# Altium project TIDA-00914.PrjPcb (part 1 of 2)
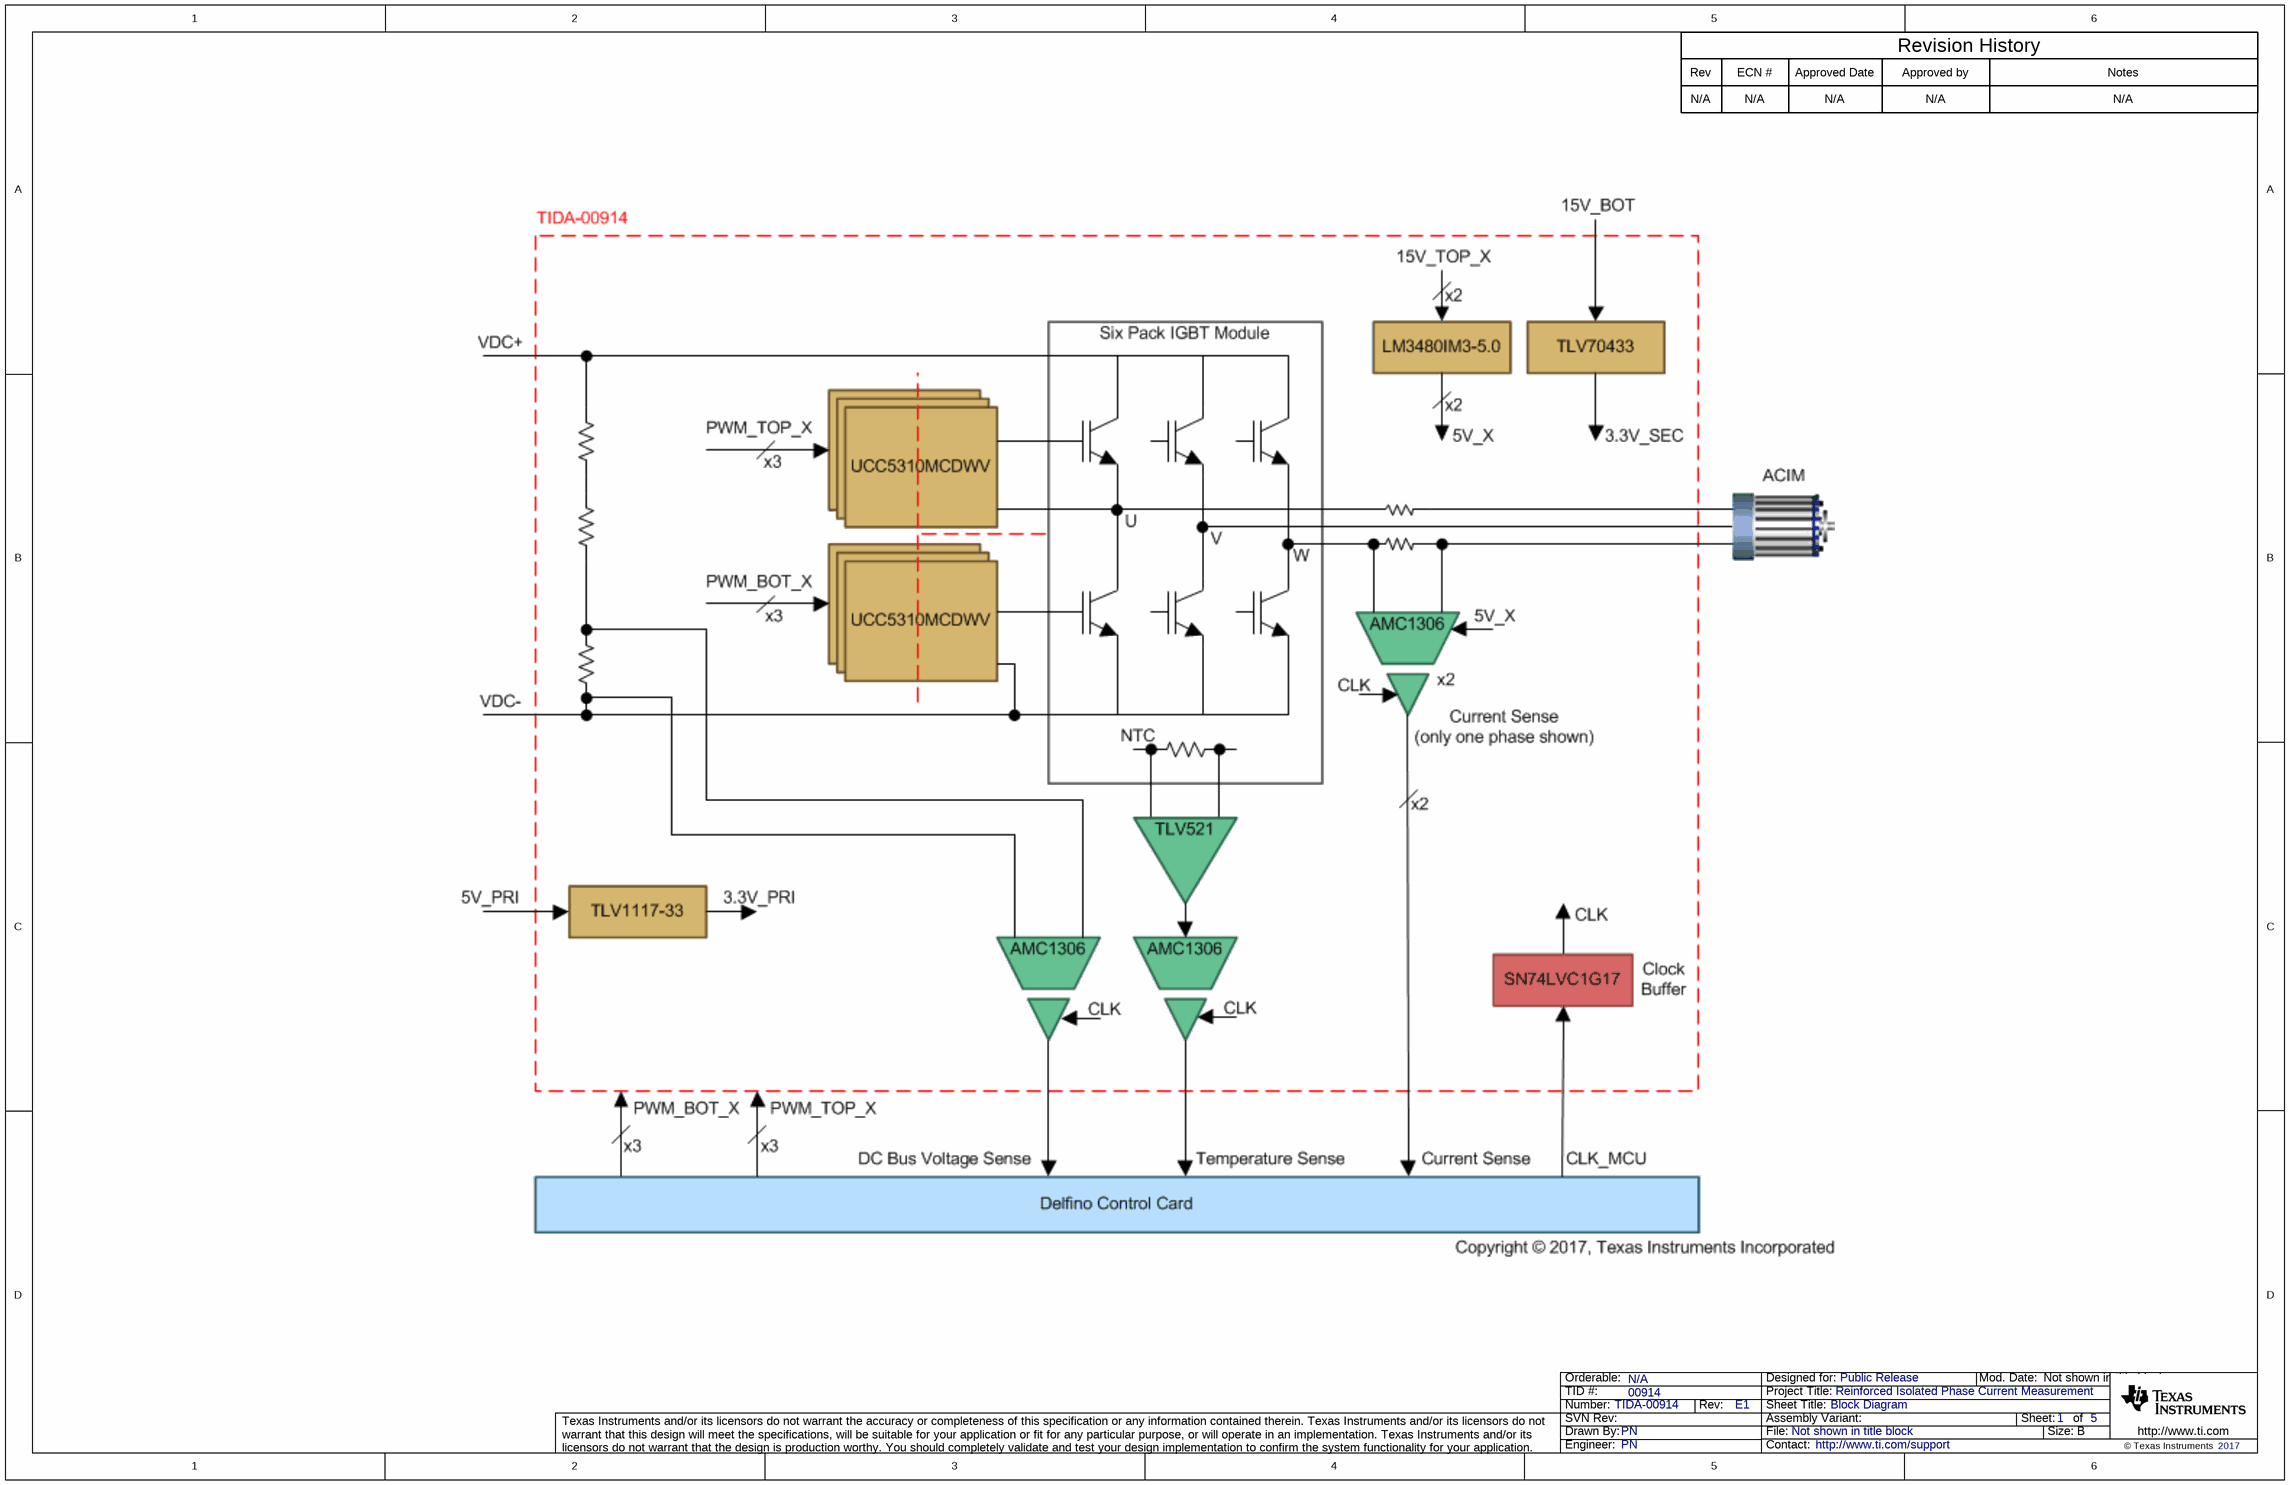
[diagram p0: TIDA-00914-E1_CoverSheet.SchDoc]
CopyrightYear: 2017; EVM_orderable: N/A; PCB_Rev: E1; PRJ_Customer: Public Release; PRJ_Engineer: PN; PRJ_Number: TIDA-00914; PRJ_Title: Reinforced Isolated Phase Current Measurement; SCH_Rev: E1; TechSupport: http://www.ti.com/support; TID: 00914
5 sheets, 303 parts. Net scope: flat (ports and power ports of the same name join across sheets).
Board file: TIDA-00914-E1.PcbDoc
Sheets:
  TIDA-00914-E1_CoverSheet.SchDoc
  TIDA-00914-E1_Gate drivers.SchDoc
  TIDA-00914-E1_IGBT Module, Temp and DC link sense.SchDoc
  TIDA-00914-E1_Current sense, MCU Interface.SchDoc
  TIDA-00914-E1_EVM_Hardware.SchDoc

## Sheet TIDA-00914-E1_CoverSheet.SchDoc: Block Diagram
size 431 x 279 mm; Date: Not shown in title block; ApprovedBy: Not shown in title block; CheckedBy: Not shown in title block; Author: Not shown in title block; CompanyName: Not shown in title block; DrawnBy: PN; Engineer: PN; Organization: Not shown in title block; Address1: Not shown in title block; Address2: Not shown in title block; Address3: Not shown in title block; Address4: Not shown in title block; DocumentNumber: 1; Revision: Use project parameter SCH_Rev; SheetNumber: 1; SheetTotal: 5; PageSetup: Record=PageOptions¦CenterHorizontal=True¦CenterVertical=True¦PrintScale=1.00¦XCorrection=1.00¦YCorrection=1.00¦PrintKind=0¦BorderSize=5000000¦LeftOffset=0¦BottomOffset=0¦Orientation=2¦PaperLength=1000¦PaperWidth=1000¦Scale=100¦PaperSource=15¦PrintQuality=600¦MediaType=1¦DitherType=10¦PaperKind=Letter¦PrintScaleMode=1

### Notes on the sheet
- Rev
- N/A
- ECN #
- Approved Date
- Approved by
- Revision History
- Notes

## Sheet TIDA-00914-E1_Gate drivers.SchDoc: Gate Drivers
size 431 x 279 mm; Date: Not shown in title block; ApprovedBy: Not shown in title block; CheckedBy: Not shown in title block; Author: Not shown in title block; CompanyName: Not shown in title block; DrawnBy: PN; Engineer: PN; Organization: Not shown in title block; Address1: Not shown in title block; Address2: Not shown in title block; Address3: Not shown in title block; Address4: Not shown in title block; DocumentNumber: 1; Revision: Use project parameter SCH_Rev; SheetNumber: 2; SheetTotal: 5; PageSetup: Record=PageOptions¦CenterHorizontal=True¦CenterVertical=True¦PrintScale=1.00¦XCorrection=1.00¦YCorrection=1.00¦PrintKind=0¦BorderSize=5000000¦LeftOffset=0¦BottomOffset=0¦Orientation=2¦PaperLength=1000¦PaperWidth=1000¦Scale=100¦PaperSource=15¦PrintQuality=600¦MediaType=1¦DitherType=10¦PaperKind=Letter¦PrintScaleMode=1
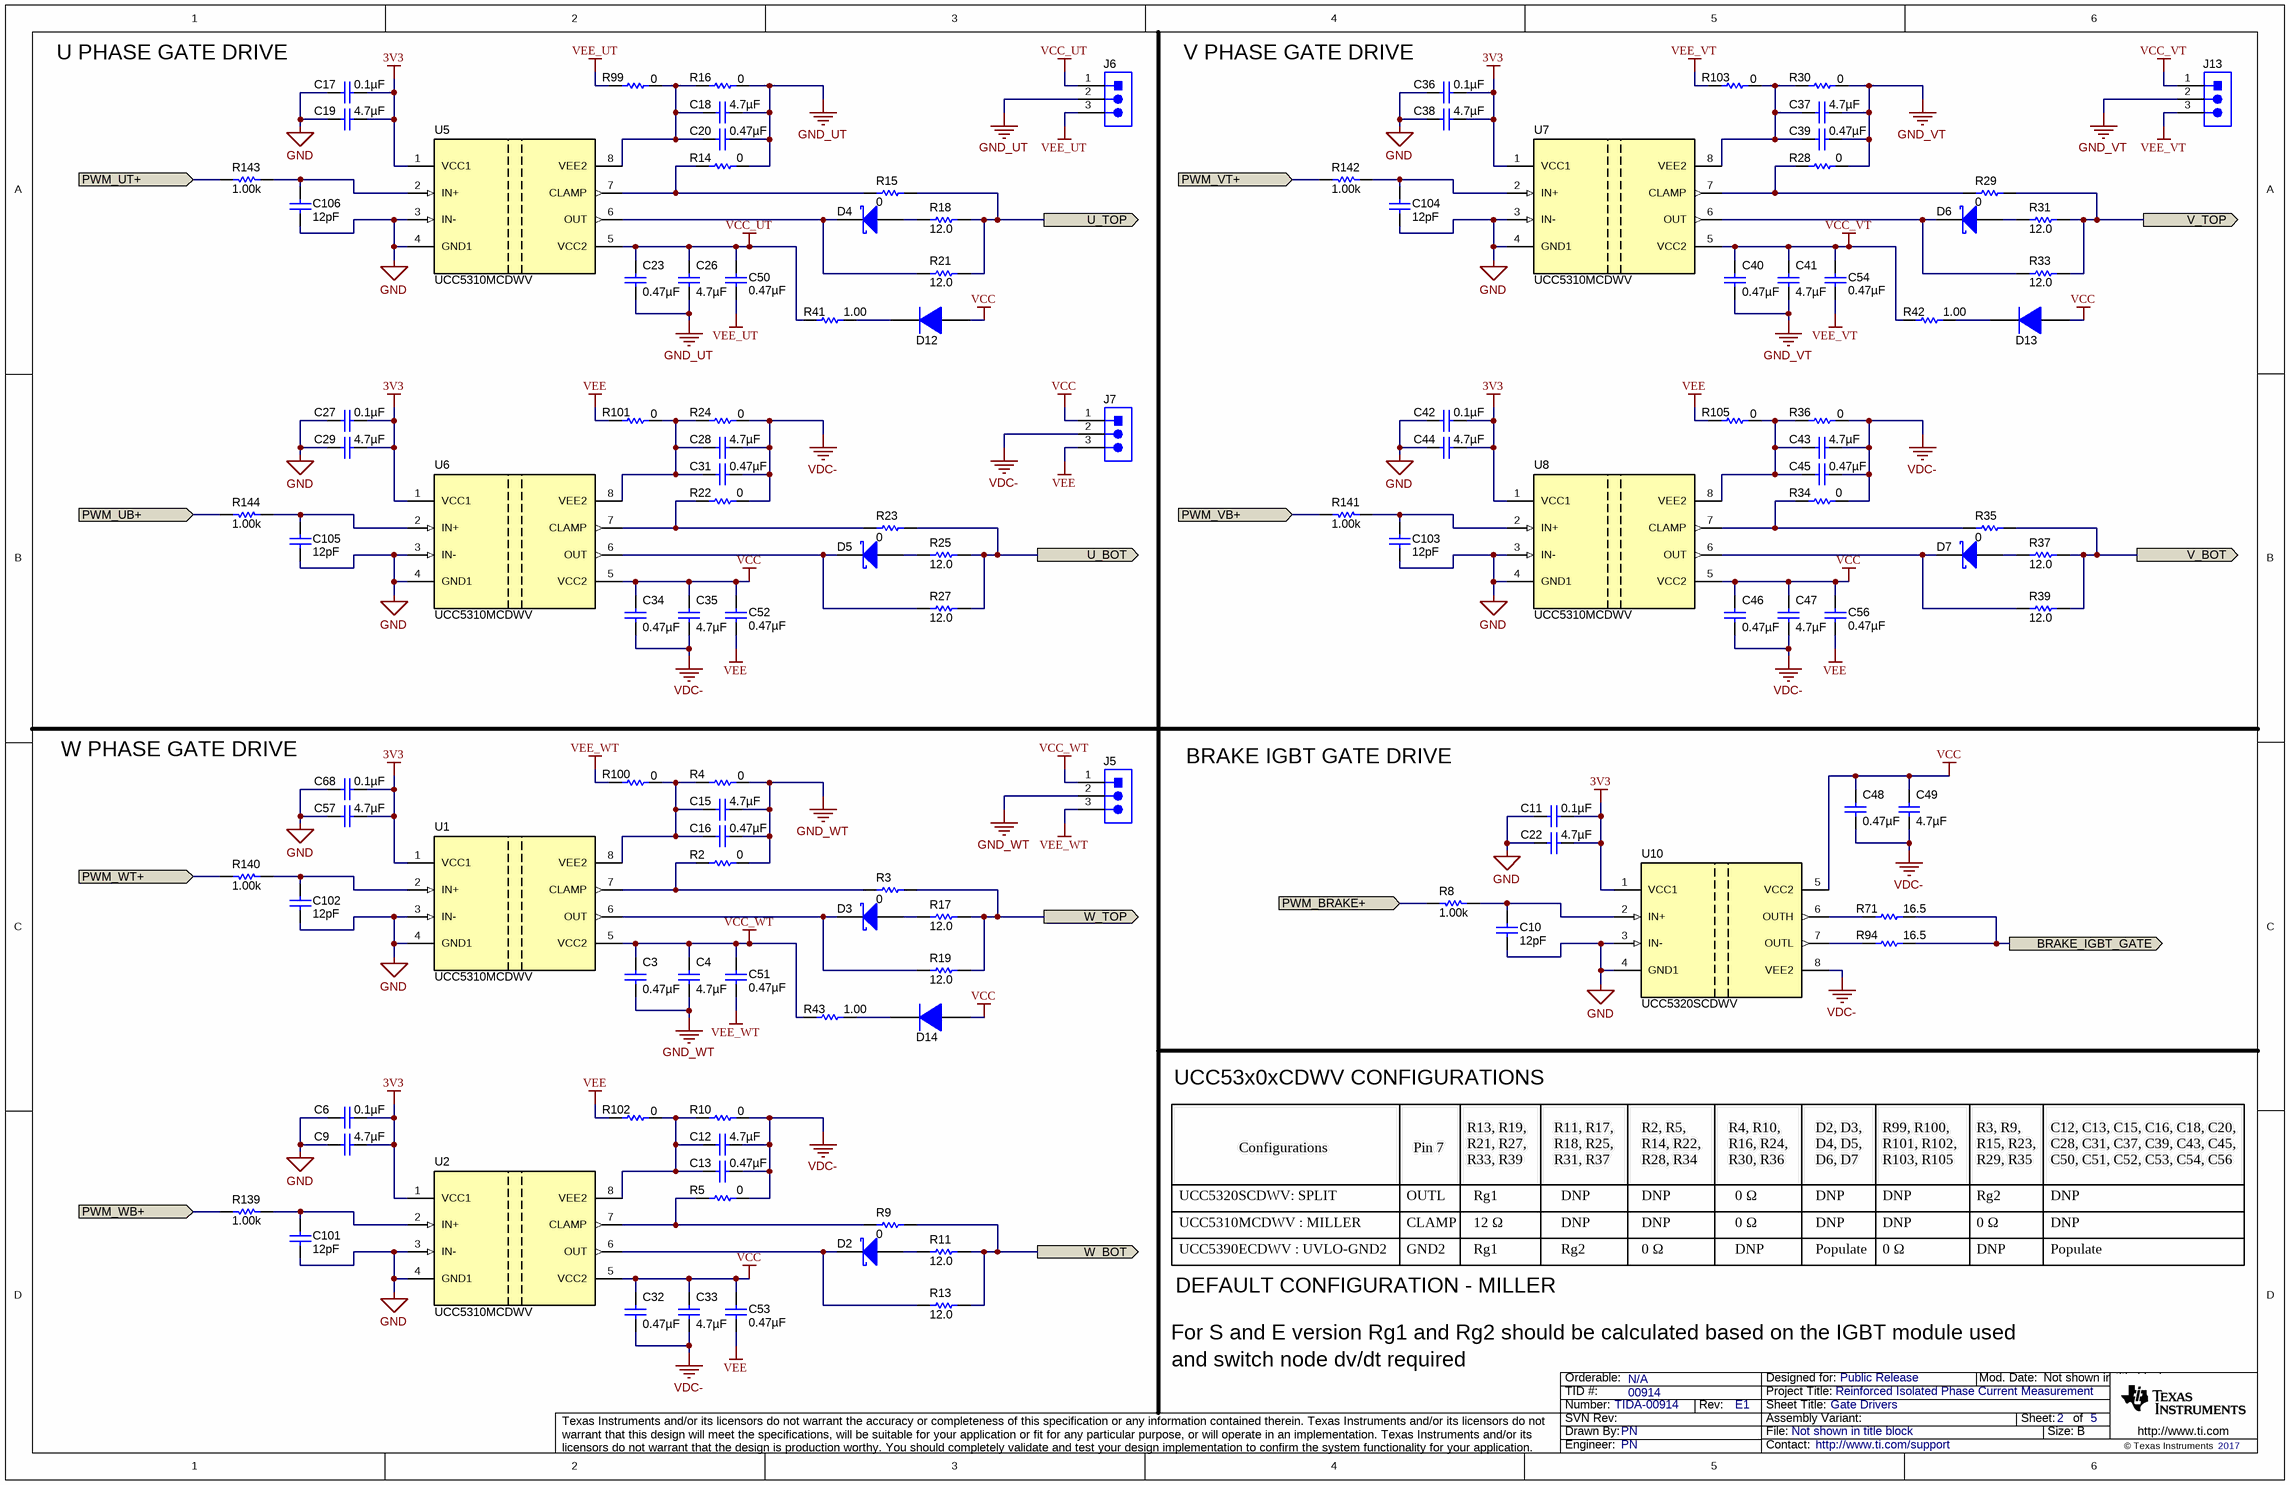
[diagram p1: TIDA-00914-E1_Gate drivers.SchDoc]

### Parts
C3  ValueDisplayed: 0.47µF  [0603]  (hidden comment: C1608X7R1H474K080AC)
C4  ValueDisplayed: 4.7µF  [0805_HV]  (hidden comment: C2012X7R1V475K125AC)
C6  ValueDisplayed: 0.1µF  [0603]  (hidden comment: C1608X7R1H104K)
C9  ValueDisplayed: 4.7µF  [0805_HV]  (hidden comment: C2012X7R1V475K125AC)
C10  ValueDisplayed: 12pF  [0603]  (hidden comment: GRM1885C1H120JA01D)
C11  ValueDisplayed: 0.1µF  [0603]  (hidden comment: C1608X7R1H104K)
C12  ValueDisplayed: 4.7µF  [0805_HV]  (hidden comment: C2012X7R1V475K125AC)
C13  ValueDisplayed: 0.47µF  [0603]  (hidden comment: C1608X7R1H474K080AC)
C15  ValueDisplayed: 4.7µF  [0805_HV]  (hidden comment: C2012X7R1V475K125AC)
C16  ValueDisplayed: 0.47µF  [0603]  (hidden comment: C1608X7R1H474K080AC)
C17  ValueDisplayed: 0.1µF  [0603]  (hidden comment: C1608X7R1H104K)
C18  ValueDisplayed: 4.7µF  [0805_HV]  (hidden comment: C2012X7R1V475K125AC)
C19  ValueDisplayed: 4.7µF  [0805_HV]  (hidden comment: C2012X7R1V475K125AC)
C20  ValueDisplayed: 0.47µF  [0603]  (hidden comment: C1608X7R1H474K080AC)
C22  ValueDisplayed: 4.7µF  [0805_HV]  (hidden comment: C2012X7R1V475K125AC)
C23  ValueDisplayed: 0.47µF  [0603]  (hidden comment: C1608X7R1H474K080AC)
C26  ValueDisplayed: 4.7µF  [0805_HV]  (hidden comment: C2012X7R1V475K125AC)
C27  ValueDisplayed: 0.1µF  [0603]  (hidden comment: C1608X7R1H104K)
C28  ValueDisplayed: 4.7µF  [0805_HV]  (hidden comment: C2012X7R1V475K125AC)
C29  ValueDisplayed: 4.7µF  [0805_HV]  (hidden comment: C2012X7R1V475K125AC)
C31  ValueDisplayed: 0.47µF  [0603]  (hidden comment: C1608X7R1H474K080AC)
C32  ValueDisplayed: 0.47µF  [0603]  (hidden comment: C1608X7R1H474K080AC)
C33  ValueDisplayed: 4.7µF  [0805_HV]  (hidden comment: C2012X7R1V475K125AC)
C34  ValueDisplayed: 0.47µF  [0603]  (hidden comment: C1608X7R1H474K080AC)
C35  ValueDisplayed: 4.7µF  [0805_HV]  (hidden comment: C2012X7R1V475K125AC)
C36  ValueDisplayed: 0.1µF  [0603]  (hidden comment: C1608X7R1H104K)
C37  ValueDisplayed: 4.7µF  [0805_HV]  (hidden comment: C2012X7R1V475K125AC)
C38  ValueDisplayed: 4.7µF  [0805_HV]  (hidden comment: C2012X7R1V475K125AC)
C39  ValueDisplayed: 0.47µF  [0603]  (hidden comment: C1608X7R1H474K080AC)
C40  ValueDisplayed: 0.47µF  [0603]  (hidden comment: C1608X7R1H474K080AC)
C41  ValueDisplayed: 4.7µF  [0805_HV]  (hidden comment: C2012X7R1V475K125AC)
C42  ValueDisplayed: 0.1µF  [0603]  (hidden comment: C1608X7R1H104K)
C43  ValueDisplayed: 4.7µF  [0805_HV]  (hidden comment: C2012X7R1V475K125AC)
C44  ValueDisplayed: 4.7µF  [0805_HV]  (hidden comment: C2012X7R1V475K125AC)
C45  ValueDisplayed: 0.47µF  [0603]  (hidden comment: C1608X7R1H474K080AC)
C46  ValueDisplayed: 0.47µF  [0603]  (hidden comment: C1608X7R1H474K080AC)
C47  ValueDisplayed: 4.7µF  [0805_HV]  (hidden comment: C2012X7R1V475K125AC)
C48  ValueDisplayed: 0.47µF  [0603]  (hidden comment: C1608X7R1H474K080AC)
C49  ValueDisplayed: 4.7µF  [0805_HV]  (hidden comment: C2012X7R1V475K125AC)
C50  ValueDisplayed: 0.47µF  [0603]  (hidden comment: C1608X7R1H474K080AC)
C51  ValueDisplayed: 0.47µF  [0603]  (hidden comment: C1608X7R1H474K080AC)
C52  ValueDisplayed: 0.47µF  [0603]  (hidden comment: C1608X7R1H474K080AC)
C53  ValueDisplayed: 0.47µF  [0603]  (hidden comment: C1608X7R1H474K080AC)
C54  ValueDisplayed: 0.47µF  [0603]  (hidden comment: C1608X7R1H474K080AC)
C56  ValueDisplayed: 0.47µF  [0603]  (hidden comment: C1608X7R1H474K080AC)
C57  ValueDisplayed: 4.7µF  [0805_HV]  (hidden comment: C2012X7R1V475K125AC)
C68  ValueDisplayed: 0.1µF  [0603]  (hidden comment: C1608X7R1H104K)
C101  ValueDisplayed: 12pF  [0603]  (hidden comment: GRM1885C1H120JA01D)
C102  ValueDisplayed: 12pF  [0603]  (hidden comment: GRM1885C1H120JA01D)
C103  ValueDisplayed: 12pF  [0603]  (hidden comment: GRM1885C1H120JA01D)
C104  ValueDisplayed: 12pF  [0603]  (hidden comment: GRM1885C1H120JA01D)
C105  ValueDisplayed: 12pF  [0603]  (hidden comment: GRM1885C1H120JA01D)
C106  ValueDisplayed: 12pF  [0603]  (hidden comment: GRM1885C1H120JA01D)
D2  MSS2P3-M3/89A  [MicroSMP]  (value not drawn)
D3  MSS2P3-M3/89A  [MicroSMP]  (value not drawn)
D4  MSS2P3-M3/89A  [MicroSMP]  (value not drawn)
D5  MSS2P3-M3/89A  [MicroSMP]  (value not drawn)
D6  MSS2P3-M3/89A  [MicroSMP]  (value not drawn)
D7  MSS2P3-M3/89A  [MicroSMP]  (value not drawn)
D12  BYG23T-M3/TR  [SMA]  (value not drawn)
D13  BYG23T-M3/TR  [SMA]  (value not drawn)
D14  BYG23T-M3/TR  [SMA]  (value not drawn)
J5  800-10-003-10-001000  [Mill-Max_800-10-003-10-001000]  (value not drawn)
J6  800-10-003-10-001000  [Mill-Max_800-10-003-10-001000]  (value not drawn)
J7  800-10-003-10-001000  [Mill-Max_800-10-003-10-001000]  (value not drawn)
J13  800-10-003-10-001000  [Mill-Max_800-10-003-10-001000]  (value not drawn)
R2  ValueDisplayed: 0  [0603]  (hidden comment: CRCW06030000Z0EA)
R3  ValueDisplayed: 0  [1206]  (hidden comment: CRCW12060000Z0EA)
R4  ValueDisplayed: 0  [0603]  (hidden comment: CRCW06030000Z0EA)
R5  ValueDisplayed: 0  [0603]  (hidden comment: CRCW06030000Z0EA)
R8  ValueDisplayed: 1.00k  [0603]  (hidden comment: CRCW06031K00FKEA)
R9  ValueDisplayed: 0  [1206]  (hidden comment: CRCW12060000Z0EA)
R10  ValueDisplayed: 0  [0603]  (hidden comment: CRCW06030000Z0EA)
R11  ValueDisplayed: 12.0  [1206]  (hidden comment: RC1206FR-0712RL)
R13  ValueDisplayed: 12.0  [1206]  (hidden comment: RC1206FR-0712RL)
R14  ValueDisplayed: 0  [0603]  (hidden comment: CRCW06030000Z0EA)
R15  ValueDisplayed: 0  [1206]  (hidden comment: CRCW12060000Z0EA)
R16  ValueDisplayed: 0  [0603]  (hidden comment: CRCW06030000Z0EA)
R17  ValueDisplayed: 12.0  [1206]  (hidden comment: RC1206FR-0712RL)
R18  ValueDisplayed: 12.0  [1206]  (hidden comment: RC1206FR-0712RL)
R19  ValueDisplayed: 12.0  [1206]  (hidden comment: RC1206FR-0712RL)
R21  ValueDisplayed: 12.0  [1206]  (hidden comment: RC1206FR-0712RL)
R22  ValueDisplayed: 0  [0603]  (hidden comment: CRCW06030000Z0EA)
R23  ValueDisplayed: 0  [1206]  (hidden comment: CRCW12060000Z0EA)
R24  ValueDisplayed: 0  [0603]  (hidden comment: CRCW06030000Z0EA)
R25  ValueDisplayed: 12.0  [1206]  (hidden comment: RC1206FR-0712RL)
R27  ValueDisplayed: 12.0  [1206]  (hidden comment: RC1206FR-0712RL)
R28  ValueDisplayed: 0  [0603]  (hidden comment: CRCW06030000Z0EA)
R29  ValueDisplayed: 0  [1206]  (hidden comment: CRCW12060000Z0EA)
R30  ValueDisplayed: 0  [0603]  (hidden comment: CRCW06030000Z0EA)
R31  ValueDisplayed: 12.0  [1206]  (hidden comment: RC1206FR-0712RL)
R33  ValueDisplayed: 12.0  [1206]  (hidden comment: RC1206FR-0712RL)
R34  ValueDisplayed: 0  [0603]  (hidden comment: CRCW06030000Z0EA)
R35  ValueDisplayed: 0  [1206]  (hidden comment: CRCW12060000Z0EA)
R36  ValueDisplayed: 0  [0603]  (hidden comment: CRCW06030000Z0EA)
R37  ValueDisplayed: 12.0  [1206]  (hidden comment: RC1206FR-0712RL)
R39  ValueDisplayed: 12.0  [1206]  (hidden comment: RC1206FR-0712RL)
R41  ValueDisplayed: 1.00  [1206]  (hidden comment: CRCW12061R00FKEA)
R42  ValueDisplayed: 1.00  [1206]  (hidden comment: CRCW12061R00FKEA)
R43  ValueDisplayed: 1.00  [1206]  (hidden comment: CRCW12061R00FKEA)
R71  ValueDisplayed: 16.5  [1206]  (hidden comment: CRCW120616R5FKEA)
R94  ValueDisplayed: 16.5  [1206]  (hidden comment: CRCW120616R5FKEA)
R99  ValueDisplayed: 0  [0603]  (hidden comment: CRCW06030000Z0EA)
R100  ValueDisplayed: 0  [0603]  (hidden comment: CRCW06030000Z0EA)
R101  ValueDisplayed: 0  [0603]  (hidden comment: CRCW06030000Z0EA)
R102  ValueDisplayed: 0  [0603]  (hidden comment: CRCW06030000Z0EA)
R103  ValueDisplayed: 0  [0603]  (hidden comment: CRCW06030000Z0EA)
R105  ValueDisplayed: 0  [0603]  (hidden comment: CRCW06030000Z0EA)
R139  ValueDisplayed: 1.00k  [0603]  (hidden comment: CRCW06031K00FKEA)
R140  ValueDisplayed: 1.00k  [0603]  (hidden comment: CRCW06031K00FKEA)
R141  ValueDisplayed: 1.00k  [0603]  (hidden comment: CRCW06031K00FKEA)
R142  ValueDisplayed: 1.00k  [0603]  (hidden comment: CRCW06031K00FKEA)
R143  ValueDisplayed: 1.00k  [0603]  (hidden comment: CRCW06031K00FKEA)
R144  ValueDisplayed: 1.00k  [0603]  (hidden comment: CRCW06031K00FKEA)
U1  UCC5310MCDWV  [DWV0008A]
U2  UCC5310MCDWV  [DWV0008A]
U5  UCC5310MCDWV  [DWV0008A]
U6  UCC5310MCDWV  [DWV0008A]
U7  UCC5310MCDWV  [DWV0008A]
U8  UCC5310MCDWV  [DWV0008A]
U10  UCC5320SCDWV  [DWV0008A]

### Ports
BRAKE_IGBT_GATE (out), PWM_BRAKE+ (in), PWM_UB+ (in), PWM_UT+ (in), PWM_VB+ (in), PWM_VT+ (in), PWM_WB+ (in), PWM_WT+ (in), U_BOT (out), U_TOP (out), V_BOT (out), V_TOP (out), W_BOT (out), W_TOP (out)

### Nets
3V3: C6.1 C9.1 C11.1 C17.1 C19.1 C22.1 C27.1 C29.1 C36.1 C38.1 C42.1 C44.1 C57.1 C68.1 U1.1(VCC1) U2.1(VCC1) U5.1(VCC1) U6.1(VCC1) U7.1(VCC1) U8.1(VCC1) U10.1(VCC1)
GND: C6.2 C9.2 C10.2 C11.2 C17.2 C19.2 C22.2 C27.2 C29.2 C36.2 C38.2 C42.2 C44.2 C57.2 C68.2 C101.2 C102.2 C103.2 C104.2 C105.2 C106.2 U1.3(IN-) U1.4(GND1) U2.3(IN-) U2.4(GND1) U5.3(IN-) U5.4(GND1) U6.3(IN-) U6.4(GND1) U7.3(IN-) U7.4(GND1) U8.3(IN-) U8.4(GND1) U10.3(IN-) U10.4(GND1)
GND_UT: C18.1 C20.1 C23.2 C26.2 J6.2 R14.2 R16.2
GND_VT: C37.1 C39.1 C40.2 C41.2 J13.2 R28.2 R30.2
GND_WT: C3.2 C4.2 C15.1 C16.1 J5.2 R2.2 R4.2
VCC: C32.1 C33.1 C34.1 C35.1 C46.1 C47.1 C48.1 C49.1 C52.1 C53.1 C56.1 D12.2(A) D13.2(A) D14.2(A) J7.1 U2.5(VCC2) U6.5(VCC2) U8.5(VCC2) U10.5(VCC2)
VCC_UT: C23.1 C26.1 C50.1 J6.1 R41.1 U5.5(VCC2)
VCC_VT: C40.1 C41.1 C54.1 J13.1 R42.1 U7.5(VCC2)
VCC_WT: C3.1 C4.1 C51.1 J5.1 R43.1 U1.5(VCC2)
VDC-: C12.1 C13.1 C28.1 C31.1 C32.2 C33.2 C34.2 C35.2 C43.1 C45.1 C46.2 C47.2 C48.2 C49.2 J7.2 R5.2 R10.2 R22.2 R24.2 R34.2 R36.2 U10.8(VEE2)
VEE: C52.2 C53.2 C56.2 J7.3 R101.1 R102.1 R105.1
VEE_UT: C50.2 J6.3 R99.1
VEE_VT: C54.2 J13.3 R103.1
VEE_WT: C51.2 J5.3 R100.1
BRAKE_IGBT_GATE: R71.2 R94.2 ; port BRAKE_IGBT_GATE
PWM_BRAKE+: R8.2 ; port PWM_BRAKE+
PWM_UB+: R144.2 ; port PWM_UB+
PWM_UT+: R143.2 ; port PWM_UT+
PWM_VB+: R141.2 ; port PWM_VB+
PWM_VT+: R142.2 ; port PWM_VT+
PWM_WB+: R139.2 ; port PWM_WB+
PWM_WT+: R140.2 ; port PWM_WT+
U_BOT: R23.2 R25.2 R27.2 ; port U_BOT
U_TOP: R15.2 R18.2 R21.2 ; port U_TOP
V_BOT: R35.2 R37.2 R39.2 ; port V_BOT
V_TOP: R29.2 R31.2 R33.2 ; port V_TOP
W_BOT: R9.2 R11.2 R13.2 ; port W_BOT
W_TOP: R3.2 R17.2 R19.2 ; port W_TOP
NetC10_1: C10.1 R8.1 U10.2(IN+)
NetC12_2: C12.2 C13.2 R10.1 R102.2 U2.8(VEE2)
NetC15_2: C15.2 C16.2 R4.1 R100.2 U1.8(VEE2)
NetC18_2: C18.2 C20.2 R16.1 R99.2 U5.8(VEE2)
NetC28_2: C28.2 C31.2 R24.1 R101.2 U6.8(VEE2)
NetC37_2: C37.2 C39.2 R30.1 R103.2 U7.8(VEE2)
NetC43_2: C43.2 C45.2 R36.1 R105.2 U8.8(VEE2)
NetC101_1: C101.1 R139.1 U2.2(IN+)
NetC102_1: C102.1 R140.1 U1.2(IN+)
NetC103_1: C103.1 R141.1 U8.2(IN+)
NetC104_1: C104.1 R142.1 U7.2(IN+)
NetC105_1: C105.1 R144.1 U6.2(IN+)
NetC106_1: C106.1 R143.1 U5.2(IN+)
NetD2_1: D2.1(K) R13.1 U2.6(OUT)
NetD2_2: D2.2(A) R11.1
NetD3_1: D3.1(K) R19.1 U1.6(OUT)
NetD3_2: D3.2(A) R17.1
NetD4_1: D4.1(K) R21.1 U5.6(OUT)
NetD4_2: D4.2(A) R18.1
NetD5_1: D5.1(K) R27.1 U6.6(OUT)
NetD5_2: D5.2(A) R25.1
NetD6_1: D6.1(K) R33.1 U7.6(OUT)
NetD6_2: D6.2(A) R31.1
NetD7_1: D7.1(K) R39.1 U8.6(OUT)
NetD7_2: D7.2(A) R37.1
NetD12_1: D12.1(K) R41.2
NetD13_1: D13.1(K) R42.2
NetD14_1: D14.1(K) R43.2
NetR2_1: R2.1 R3.1 U1.7(CLAMP)
NetR5_1: R5.1 R9.1 U2.7(CLAMP)
NetR14_1: R14.1 R15.1 U5.7(CLAMP)
NetR22_1: R22.1 R23.1 U6.7(CLAMP)
NetR28_1: R28.1 R29.1 U7.7(CLAMP)
NetR34_1: R34.1 R35.1 U8.7(CLAMP)
NetR71_1: R71.1 U10.6(OUTH)
NetR94_1: R94.1 U10.7(OUTL)

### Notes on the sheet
- U PHASE GATE DRIVE
- V PHASE GATE DRIVE
- W PHASE GATE DRIVE
- BRAKE IGBT GATE DRIVE
- UCC53x0xCDWV CONFIGURATIONS
- Configurations
- Pin 7
- UCC5320SCDWV: SPLIT
- UCC5310MCDWV : MILLER
- OUTL
- CLAMP
- R13, R19, R21, R27, R33, R39
- Rg1
- 12 Ω
- R11, R17, R18, R25, R31, R37
- DNP
- R2, R5, R14, R22, R28, R34
- R4, R10, R16, R24, R30, R36
- 0 Ω
- D2, D3, D4, D5, D6, D7
- R99, R100, R101, R102, R103, R105
- Rg2
- R3, R9, R15, R23, R29, R35
- C12, C13, C15, C16, C18, C20, C28, C31, C37, C39, C43, C45, C50, C51, C52, C53, C54, C56
- UCC5390ECDWV : UVLO-GND2
- DEFAULT CONFIGURATION - MILLER
- GND2
- Populate
- and switch node dv/dt required
- For S and E version Rg1 and Rg2 should be calculated based on the IGBT module used

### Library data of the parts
C3 C13 C16 C20 C23 C31 C32 C34 C39 C40 C45 C46 C48 C50-C54 C56 = C1608X7R1H474K080AC: CAP, CERM, 0.47 µF, 50 V, +/- 10%, X7R, 0603; Manufacturer: TDK; Polarized: N; CompType: Capacitor; Value: 0.47uF; U/M: EA; Cap_F: 0.00000047; Tolerance_%: 10; ESR_ohm: 0.010974; Value1: 0.010974 ohm; VDC_V: 50; Value2: 50V; IRMS_A: 1.57483; TaMin_C: -55; TaMax_C: 125; SizeArea_mm2: 1.28; SizeAreaWB_mm2: 4.68; SizeX_mm: 1.6; SizeY_mm: 0.8; SizeZ_mm: 1; AEC Category: Q200
C4 C9 C12 C15 C18 C19 C22 C26 C28 C29 C33 C35 C37 C38 C41 C43 C44 C47 C49 C57 = C2012X7R1V475K125AC: CAP, CERM, 4.7 µF, 35 V, +/- 10%, X7R, 0805; Manufacturer: TDK; Polarized: N; CompType: Capacitor; Value: 4.7uF; U/M: EA; Cap_F: 0.0000047; Tolerance_%: 10; ESR_ohm: 0.002346; Value1: 0.002346 ohm; VDC_V: 35; Value2: 35V; IRMS_A: 4.26021; TaMin_C: -55; TaMax_C: 125; Cap_Case: 0805; SizeArea_mm2: 2.5; SizeAreaWB_mm2: 6.75; SizeX_mm: 2; SizeY_mm: 1.25; SizeZ_mm: 1.45; AEC Category: Q200
C6 C11 C17 C27 C36 C42 C68 = C1608X7R1H104K: CAP, CERM, 0.1 µF, 50 V, +/- 10%, X7R, 0603; Manufacturer: TDK; Polarized: N; CompType: Capacitor; Value: 0.1uF; U/M: EA; Cap_F: 0.0000001; Tolerance_%: 10; ESR_ohm: 0.017; Value1: 0.017 ohm; VDC_V: 50; Value2: 50V; TaMin_C: -55; TaMax_C: 125; AEC Category: Q200
C10 C101-C106 = GRM1885C1H120JA01D: CAP, CERM, 12 pF, 50 V, +/- 5%, C0G/NP0, 0603; Manufacturer: MuRata; Polarized: N; CompType: Capacitor; Value: 12pF; U/M: EA; Cap_F: 0.000000000012; Tolerance_%: 5; Value1: Unknown; VDC_V: 50; Value2: 50V; TaMin_C: -55; TaMax_C: 125; AEC Category: Q200; SizeArea_mm2: 1.28; SizeAreaWB_mm2: 4.68; SizeX_mm: 1.6; SizeY_mm: 0.8; SizeZ_mm: 1
D2-D7 = MSS1P3L-M3/89A: Diode, Schottky, 30 V, 2 A, AEC-Q101, MicroSMP; Manufacturer: Vishay-Semiconductor; U/M: EA; Vf_V: 0.6; Value: 30V; Value1: 2A; Value2: 0.6V; Io_A: 1; Vr_V: 30; TJmax_C: 150; RJC_CperW: 40; AEC Category: Q101; AEC Qualified: Y
D12-D14 = BYG23T-M3/TR: Diode, Ultrafast, 1300 V, 1 A, SMA; Manufacturer: Vishay-Semiconductor; U/M: EA; Vf_V: 1.9; Value: 1300V; Value1: 1A; Value2: 1.9V; Io_A: 1; Vr_V: 1300; TJmax_C: 150; AEC Category: Q101; AEC Qualified: N
J5-J7 J13 = 800-10-003-10-001000: Header, 100mil, 3x1, TH; Manufacturer: Mill-Max; SymbolCreator: a0799628
R2 R4 R5 R10 R14 R16 R22 R24 R28 R30 R34 R36 R99-R103 R105 = CRCW06030000Z0EA: RES, 0, 5%, 0.1 W, 0603; Manufacturer: Vishay-Dale; CompType: Resistor; Value: 0; Value_Code: 0000; Tolerance_%: 5; Power_W: 0.1; Value2: 0.1W; VDC_V: 75; TempCo: 200 ppm/C; EIA_Code: E24; U/M: EA; AEC Category: Q200; SizeArea_mm2: 1.28; SizeX_mm: 1.6; SizeY_mm: 0.8; SizeZ_mm: 1
R3 R9 R15 R23 R29 R35 = CRCW12060000Z0EA: RES, 0, 5%, 0.25 W, 1206; Manufacturer: Vishay-Dale; CompType: Resistor; Value: 0; Value_Code: 0000; Tolerance_%: 5; Power_W: 0.25; Value2: 0.25W; VDC_V: 200; TempCo: 200 ppm/C; EIA_Code: E24; U/M: EA; AEC Category: Q200; SizeArea_mm2: 5.12; SizeX_mm: 3.2; SizeY_mm: 1.6; SizeZ_mm: 1.35
R8 R139-R144 = CRCW06031K00FKEA: RES, 1.00 k, 1%, 0.1 W, 0603; Manufacturer: Vishay-Dale; CompType: Resistor; Value: 1.00k; Res_ohm: 1000; Value_Code: 1k00; Tolerance_%: 1; Power_W: 0.1; Value2: 0.1W; VDC_V: 75; TempCo: 100 ppm/C; EIA_Code: E96; U/M: EA; AEC Category: Q200; SizeArea_mm2: 1.28; SizeX_mm: 1.6; SizeY_mm: 0.8
R11 R13 R17-R19 R21 R25 R27 R31 R33 R37 R39 = RC1206FR-0712RL: RES, 12.0, 1%, 0.25 W, 1206; Manufacturer: Yageo America; CompType: Resistor; Value: 12.0; Res_ohm: 12; Value_Code: 12R0; Tolerance_%: 1; Power_W: 0.25; Value2: 0.25W; VDC_V: 200; TempCo: 100 ppm/C; U/M: EA; AEC Category: Q200; SizeArea_mm2: 5.12; SizeX_mm: 3.2; SizeY_mm: 1.6; SizeZ_mm: 1.35
R41-R43 = CRCW12061R00FKEA: RES, 1.00, 1%, 0.25 W, 1206; Manufacturer: Vishay-Dale; CompType: Resistor; Value: 1.00; Res_ohm: 1; Value_Code: 1R00; Power_W: 0.25; Value2: 0.25W; VDC_V: 200; TempCo: 100 ppm/C; SizeArea_mm2: 5.12; SizeX_mm: 3.2; SizeY_mm: 1.6; SizeZ_mm: 1.35; EIA_Code: E96; U/M: EA; AEC Category: Q200
R71 R94 = CRCW120616R5FKEA: RES, 16.5, 1%, 0.25 W, 1206; Manufacturer: Vishay-Dale; CompType: Resistor; Value: 16.5; Value_Code: 16R5; Tolerance_%: 1; Power_W: 0.25; Value2: 0.25W; VDC_V: 200; TempCo: 100 ppm/C; EIA_Code: E96; U/M: EA; AEC Category: Q200; SizeArea_mm2: 5.12; SizeX_mm: 3.2; SizeY_mm: 1.6; SizeZ_mm: 1.35
U1 U2 U5-U8 = CMP-0078847-1: 5-kVRMS Single-Channel Isolated Gate Drivers, DWV0008A (SOIC-8); Alternate PartNumber: UCC5310MCDWVR; Alternate Manufacturer: Texas Instruments; SizeAreaWB_mm2: 105.975; SizeZ_mm: 2.8; SizeX_mm: 11.5; SizeY_mm: 5.85; SizeArea_mm2: 67.275; CompType: IC; AEC Qualified: N; AEC Category: Q200
U10 = CMP-0078838-1: 5-kVRMS Single-Channel Isolated Gate Drivers, DWV0008A (SOIC-8); Alternate PartNumber: UCC5320SCDWVR; Alternate Manufacturer: Texas Instruments; SizeAreaWB_mm2: 105.975; SizeZ_mm: 2.8; SizeX_mm: 11.5; SizeY_mm: 5.85; SizeArea_mm2: 67.275; CompType: IC; AEC Qualified: N; AEC Category: Q200

## Sheet TIDA-00914-E1_IGBT Module, Temp and DC link sense.SchDoc: Inverter, Temp and DC link Vtg Sense
size 431 x 279 mm; Date: Not shown in title block; ApprovedBy: Not shown in title block; CheckedBy: Not shown in title block; Author: Not shown in title block; CompanyName: Not shown in title block; DrawnBy: PN; Engineer: PN; Organization: Not shown in title block; Address1: Not shown in title block; Address2: Not shown in title block; Address3: Not shown in title block; Address4: Not shown in title block; DocumentNumber: 1; Revision: Use project parameter SCH_Rev; SheetNumber: 3; SheetTotal: 5; PageSetup: Record=PageOptions¦CenterHorizontal=True¦CenterVertical=True¦PrintScale=1.00¦XCorrection=1.00¦YCorrection=1.00¦PrintKind=0¦BorderSize=5000000¦LeftOffset=0¦BottomOffset=0¦Orientation=2¦PaperLength=1000¦PaperWidth=1000¦Scale=100¦PaperSource=15¦PrintQuality=600¦MediaType=1¦DitherType=10¦PaperKind=Letter¦PrintScaleMode=1
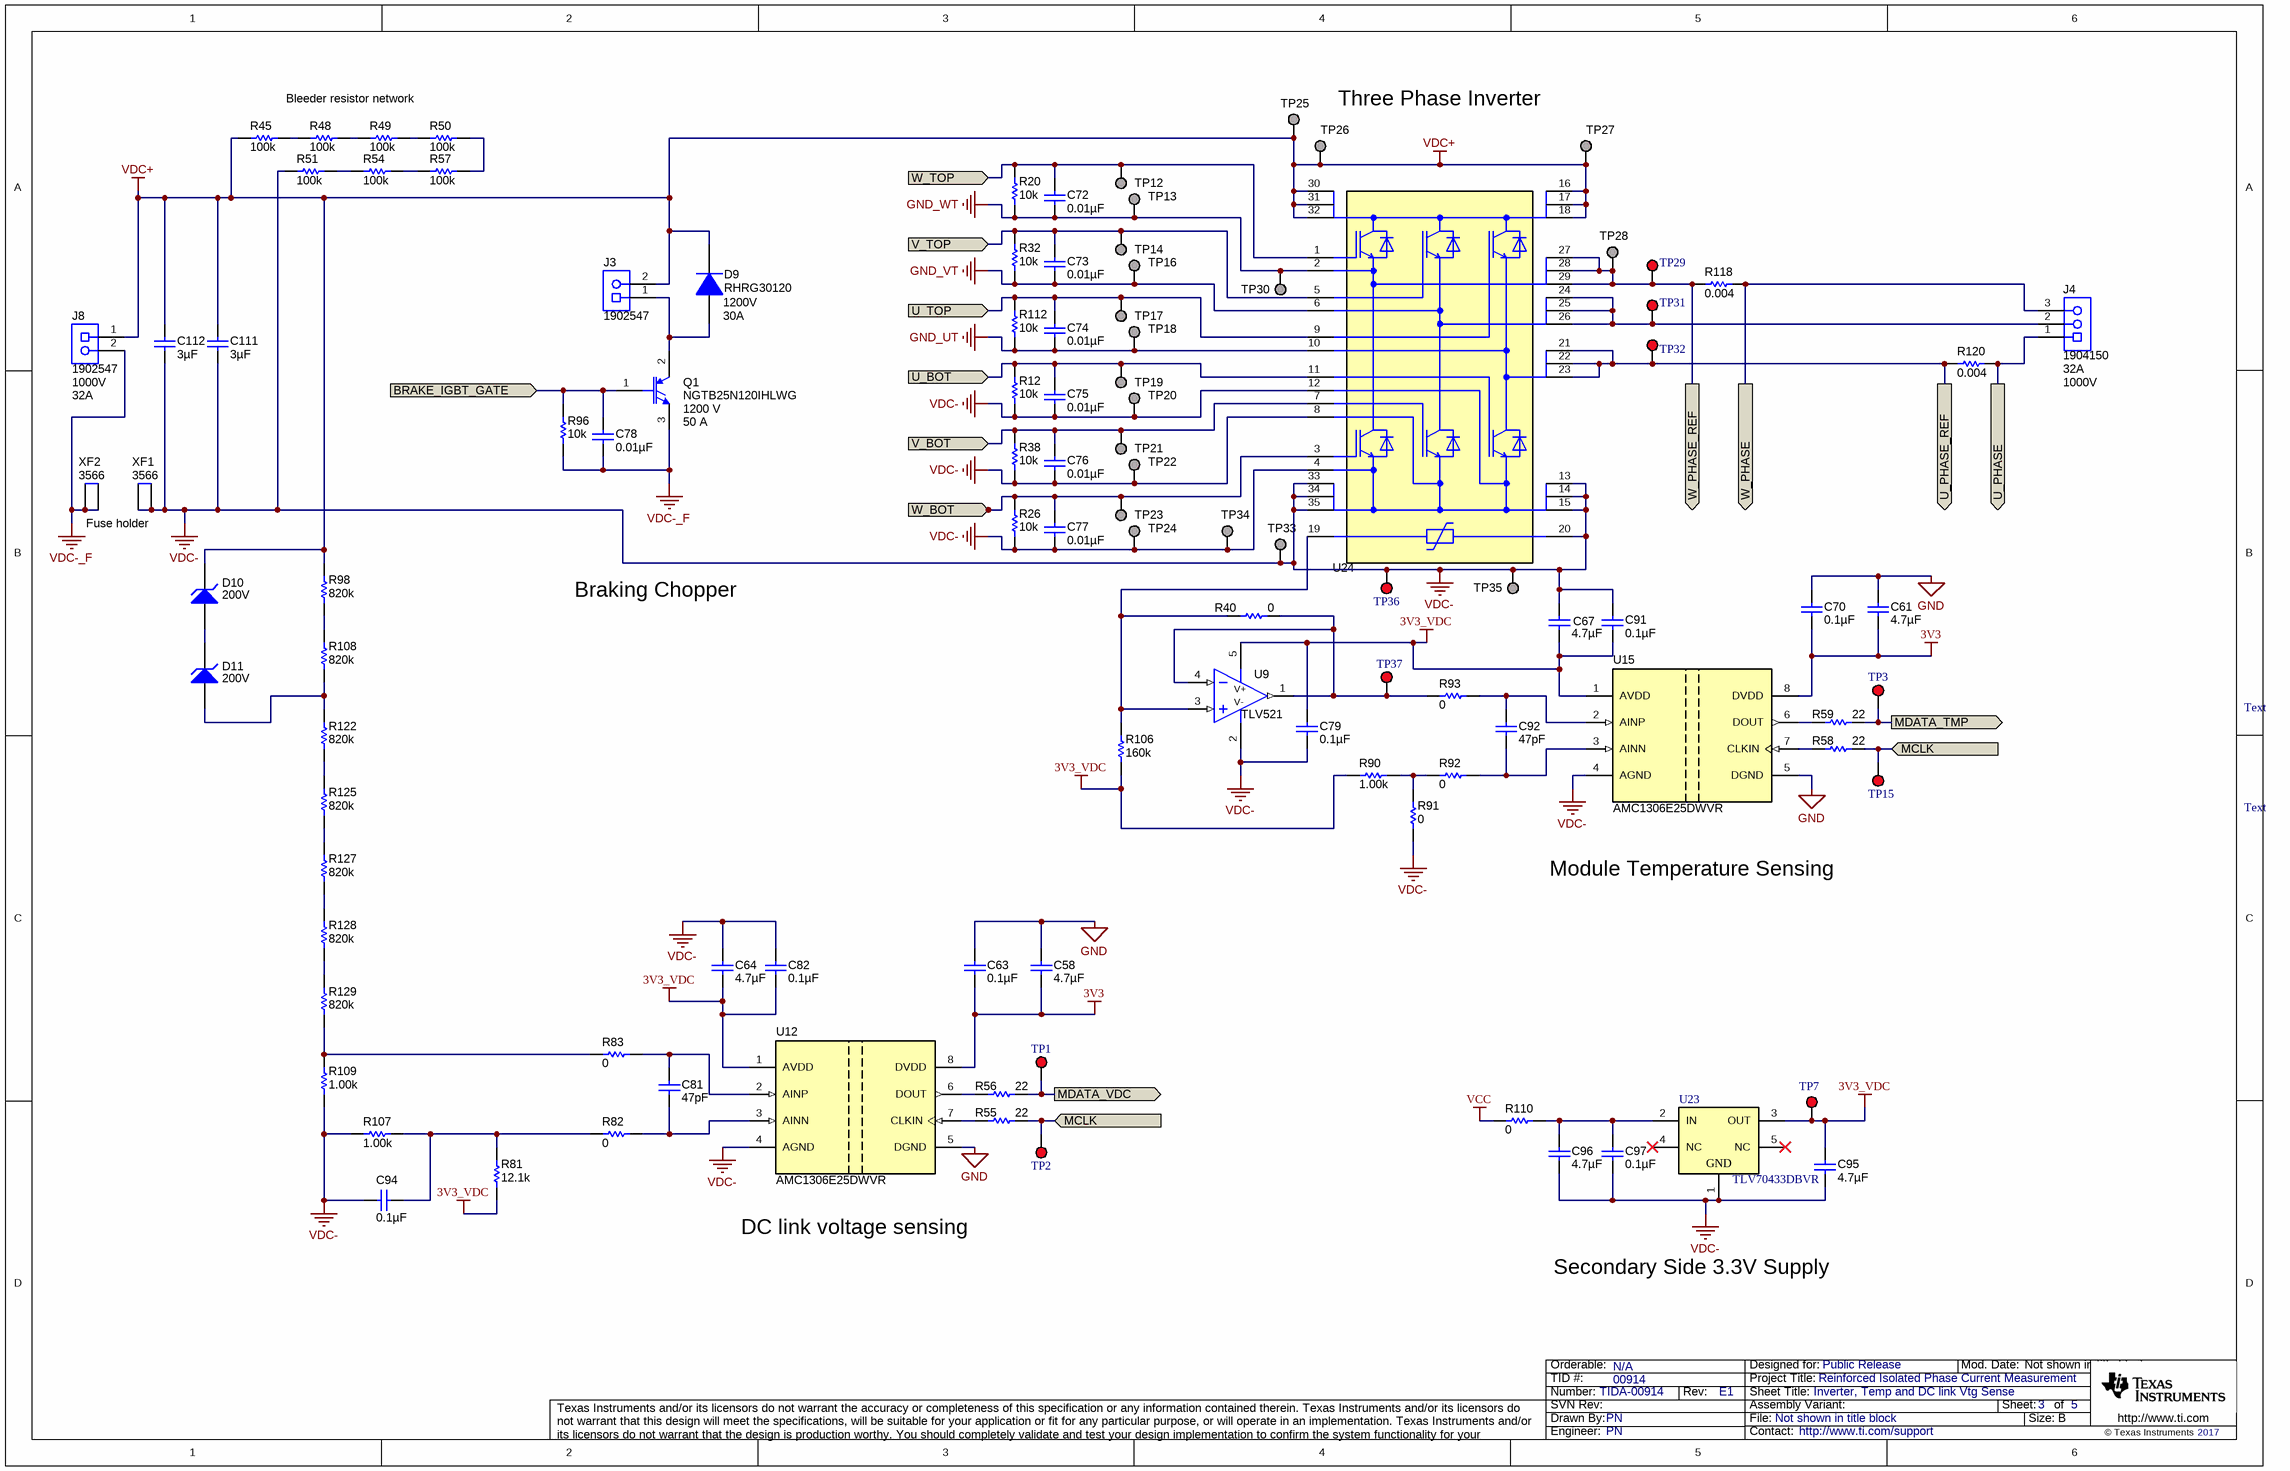
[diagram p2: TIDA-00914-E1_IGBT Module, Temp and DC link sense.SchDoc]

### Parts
C58  ValueDisplayed: 4.7µF  [0805_HV]  (hidden comment: C2012X7R1V475K125AC)
C61  ValueDisplayed: 4.7µF  [0805_HV]  (hidden comment: C2012X7R1V475K125AC)
C63  ValueDisplayed: 0.1µF  [0603]  (hidden comment: C1608X7R1H104K)
C64  ValueDisplayed: 4.7µF  [0805_HV]  (hidden comment: C2012X7R1V475K125AC)
C67  ValueDisplayed: 4.7µF  [0805_HV]  (hidden comment: C2012X7R1V475K125AC)
C70  ValueDisplayed: 0.1µF  [0603]  (hidden comment: C1608X7R1H104K)
C72  ValueDisplayed: 0.01µF  [0603]  (hidden comment: CGA3E2C0G1H103J080AA)
C73  ValueDisplayed: 0.01µF  [0603]  (hidden comment: CGA3E2C0G1H103J080AA)
C74  ValueDisplayed: 0.01µF  [0603]  (hidden comment: CGA3E2C0G1H103J080AA)
C75  ValueDisplayed: 0.01µF  [0603]  (hidden comment: CGA3E2C0G1H103J080AA)
C76  ValueDisplayed: 0.01µF  [0603]  (hidden comment: CGA3E2C0G1H103J080AA)
C77  ValueDisplayed: 0.01µF  [0603]  (hidden comment: CGA3E2C0G1H103J080AA)
C78  ValueDisplayed: 0.01µF  [0603]  (hidden comment: CGA3E2C0G1H103J080AA)
C79  ValueDisplayed: 0.1µF  [0603]  (hidden comment: C1608X7R1H104K)
C81  ValueDisplayed: 47pF  [0603]  (hidden comment: GRM1885C1H470JA01D)
C82  ValueDisplayed: 0.1µF  [0603]  (hidden comment: C1608X7R1H104K)
C91  ValueDisplayed: 0.1µF  [0603]  (hidden comment: C1608X7R1H104K)
C92  ValueDisplayed: 47pF  [0603]  (hidden comment: GRM1885C1H470JA01D)
C94  ValueDisplayed: 0.1µF  [0603]  (hidden comment: C1608X7R1H104K)
C95  ValueDisplayed: 4.7µF  [0805_HV]  (hidden comment: C2012X7R1V475K125AC)
C96  ValueDisplayed: 4.7µF  [0805_HV]  (hidden comment: C2012X7R1V475K125AC)
C97  ValueDisplayed: 0.1µF  [0603]  (hidden comment: C1608X7R1H104K)
C111  ValueDisplayed: 3µF  [B32774_3150x1800x2750]  (hidden comment: B32774D1305K000)
C112  ValueDisplayed: 3µF  [B32774_3150x1800x2750]  (hidden comment: B32774D1305K000)
D9  RHRG30120  value 1200V  Value1: 30A  [TO-247-2]
D10  value 200V  [SMB]  (hidden comment: 1SMB5956BT3G)
D11  value 200V  [SMB]  (hidden comment: 1SMB5956BT3G)
J3  1902547  [Phoenix_1902547]
J4  1904150  Current_A: 32A  Voltage_V: 1000V  [Phoenix_1904150]
J8  1902547  Current_A: 32A  Voltage_V: 1000V  [Phoenix_1902547]
Q1  NGTB25N120IHLWG  value 1200 V  Value1: 50 A  [TO-247]
R12  ValueDisplayed: 10k  [0603]  (hidden comment: CRCW060310K0JNEA)
R20  ValueDisplayed: 10k  [0603]  (hidden comment: CRCW060310K0JNEA)
R26  ValueDisplayed: 10k  [0603]  (hidden comment: CRCW060310K0JNEA)
R32  ValueDisplayed: 10k  [0603]  (hidden comment: CRCW060310K0JNEA)
R38  ValueDisplayed: 10k  [0603]  (hidden comment: CRCW060310K0JNEA)
R40  ValueDisplayed: 0  [0603]  (hidden comment: CRCW06030000Z0EA)
R45  ValueDisplayed: 100k  [1206L]  (hidden comment: CRCW1206100KJNEAHP)
R48  ValueDisplayed: 100k  [1206L]  (hidden comment: CRCW1206100KJNEAHP)
R49  ValueDisplayed: 100k  [1206L]  (hidden comment: CRCW1206100KJNEAHP)
R50  ValueDisplayed: 100k  [1206L]  (hidden comment: CRCW1206100KJNEAHP)
R51  ValueDisplayed: 100k  [1206L]  (hidden comment: CRCW1206100KJNEAHP)
R54  ValueDisplayed: 100k  [1206L]  (hidden comment: CRCW1206100KJNEAHP)
R55  ValueDisplayed: 22  [0603]  (hidden comment: CRCW060322R0JNEA)
R56  ValueDisplayed: 22  [0603]  (hidden comment: CRCW060322R0JNEA)
R57  ValueDisplayed: 100k  [1206L]  (hidden comment: CRCW1206100KJNEAHP)
R58  ValueDisplayed: 22  [0603]  (hidden comment: CRCW060322R0JNEA)
R59  ValueDisplayed: 22  [0603]  (hidden comment: CRCW060322R0JNEA)
R81  ValueDisplayed: 12.1k  [0603]  (hidden comment: CRCW060312K1FKEA)
R82  ValueDisplayed: 0  [0603]  (hidden comment: CRCW06030000Z0EA)
R83  ValueDisplayed: 0  [0603]  (hidden comment: CRCW06030000Z0EA)
R90  ValueDisplayed: 1.00k  [0603]  (hidden comment: CRCW06031K00FKEA)
R91  ValueDisplayed: 0  [0603]  (hidden comment: CRCW06030000Z0EA)
R92  ValueDisplayed: 0  [0603]  (hidden comment: CRCW06030000Z0EA)
R93  ValueDisplayed: 0  [0603]  (hidden comment: CRCW06030000Z0EA)
R96  ValueDisplayed: 10k  [0603]  (hidden comment: CRCW060310K0JNEA)
R98  ValueDisplayed: 820k  [1206]  (hidden comment: RC1206FR-07820KL)
R106  ValueDisplayed: 160k  [0603]  (hidden comment: CRCW0603160KFKEA)
R107  ValueDisplayed: 1.00k  [0603]  (hidden comment: CRCW06031K00FKEA)
R108  ValueDisplayed: 820k  [1206]  (hidden comment: RC1206FR-07820KL)
R109  ValueDisplayed: 1.00k  [0603]  (hidden comment: CRCW06031K00FKEA)
R110  ValueDisplayed: 0  [0603]  (hidden comment: CRCW06030000Z0EA)
R112  ValueDisplayed: 10k  [0603]  (hidden comment: CRCW060310K0JNEA)
R118  ValueDisplayed: 0.004  [PU5931_146]  (hidden comment: PU5931FKMP70R004L)
R120  ValueDisplayed: 0.004  [PU5931_146]  (hidden comment: PU5931FKMP70R004L)
R122  ValueDisplayed: 820k  [1206]  (hidden comment: RC1206FR-07820KL)
R125  ValueDisplayed: 820k  [1206]  (hidden comment: RC1206FR-07820KL)
R127  ValueDisplayed: 820k  [1206]  (hidden comment: RC1206FR-07820KL)
R128  ValueDisplayed: 820k  [1206]  (hidden comment: RC1206FR-07820KL)
R129  ValueDisplayed: 820k  [1206]  (hidden comment: RC1206FR-07820KL)
TP1  5000  [Keystone5000]  (value not drawn)
TP2  5000  [Keystone5000]  (value not drawn)
TP3  5000  [Keystone5000]  (value not drawn)
TP7  5000  [Keystone5000]  (value not drawn)
TP12  TESTPOINT  [TP_VIA_060RND040]  (value not drawn)  (no BOM)
TP13  TESTPOINT  [TP_VIA_060RND040]  (value not drawn)  (no BOM)
TP14  TESTPOINT  [TP_VIA_060RND040]  (value not drawn)  (no BOM)
TP15  5000  [Keystone5000]  (value not drawn)
TP16  TESTPOINT  [TP_VIA_060RND040]  (value not drawn)  (no BOM)
TP17  TESTPOINT  [TP_VIA_060RND040]  (value not drawn)  (no BOM)
TP18  TESTPOINT  [TP_VIA_060RND040]  (value not drawn)  (no BOM)
TP19  TESTPOINT  [TP_VIA_060RND040]  (value not drawn)  (no BOM)
TP20  TESTPOINT  [TP_VIA_060RND040]  (value not drawn)  (no BOM)
TP21  TESTPOINT  [TP_VIA_060RND040]  (value not drawn)  (no BOM)
TP22  TESTPOINT  [TP_VIA_060RND040]  (value not drawn)  (no BOM)
TP23  TESTPOINT  [TP_VIA_060RND040]  (value not drawn)  (no BOM)
TP24  TESTPOINT  [TP_VIA_060RND040]  (value not drawn)  (no BOM)
TP25  TESTPOINT  [TP_VIA_060RND040]  (value not drawn)  (no BOM)
TP26  TESTPOINT  [TP_VIA_060RND040]  (value not drawn)  (no BOM)
TP27  TESTPOINT  [TP_VIA_060RND040]  (value not drawn)  (no BOM)
TP28  TESTPOINT  [TP_VIA_060RND040]  (value not drawn)  (no BOM)
TP29  5000  [Keystone5000]  (value not drawn)
TP30  TESTPOINT  [TP_VIA_060RND040]  (value not drawn)  (no BOM)
TP31  5000  [Keystone5000]  (value not drawn)
TP32  5000  [Keystone5000]  (value not drawn)
TP33  TESTPOINT  [TP_VIA_060RND040]  (value not drawn)  (no BOM)
TP34  TESTPOINT  [TP_VIA_060RND040]  (value not drawn)  (no BOM)
TP35  TESTPOINT  [TP_VIA_060RND040]  (value not drawn)  (no BOM)
TP36  5000  [Keystone5000]  (value not drawn)
TP37  5000  [Keystone5000]  (value not drawn)
U9  TLV521  [DCK0005A_N]
U12  AMC1306E25DWVR  [DWV0008A]
U15  AMC1306E25DWVR  [DWV0008A]
U23  TLV70433DBVR  [DBV0005A_N]
U24  CM100TX-24S1  [CM100TX-24S1]  (value not drawn)
XF1  3566  [Keystone_3566]
XF2  3566  [Keystone_3566]

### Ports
BRAKE_IGBT_GATE (in), MCLK (in), MDATA_TMP (out), MDATA_VDC (out), U_BOT (in), U_PHASE (out), U_PHASE_REF (out), U_TOP (in), V_BOT (in), V_TOP (in), W_BOT (in), W_PHASE (out), W_PHASE_REF (out), W_TOP (in)

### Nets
3V3: C58.2 C61.2 C63.2 C70.2 U12.8(DVDD) U15.8(DVDD)
3V3_VDC: C64.2 C67.2 C79.1 C82.2 C91.2 C95.1 R81.1 R90.2 R106.1 TP7.1 U9.5(V+) U12.1(AVDD) U15.1(AVDD) U23.3(OUT)
GND: C58.1 C61.1 C63.1 C70.1 U12.5(DGND) U15.5(DGND)
GND_UT: C74.2 R112.1 TP18.1 U24.10(EWP)
GND_VT: C73.2 R32.1 TP16.1 U24.6(EVP)
GND_WT: C72.2 R20.1 TP13.1 TP30.1 U24.2(EUP)
VCC: R110.1
VDC+: C111.1 C112.1 D9.1(K) D10.1(K) J3.2 J8.1 R45.1 R98.2 TP25.1 TP26.1 TP27.1 U24.16(P1) U24.17(P1) U24.18(P1) U24.30(P) U24.31(P) U24.32(P)
VDC-: C64.1 C67.1 C75.2 C76.2 C77.2 C79.2 C82.1 C91.1 C94.1 C95.2 C96.2 C97.2 C111.2 C112.2 R12.1 R26.1 R38.1 R51.1 R91.1 R107.1 R109.1 TP20.1 TP22.1 TP24.1 TP33.1 TP34.1 TP35.1 TP36.1 U9.2(V-) U12.4(AGND) U15.4(AGND) U23.1(GND) U24.4(EUN) U24.8(EVN) U24.12(EWN) U24.13(N1) U24.14(N1) U24.15(N1) U24.20(TH2) U24.33(N) U24.34(N) U24.35(N) XF1.1 XF1.2
VDC-_F: C78.2 J8.2 Q1.3(E) R96.1 XF2.1 XF2.2
BRAKE_IGBT_GATE: C78.1 Q1.1(G) R96.2 ; port BRAKE_IGBT_GATE
MCLK: R55.2 R58.2 TP2.1 TP15.1 ; port MCLK
MDATA_TMP: R59.2 TP3.1 ; port MDATA_TMP
MDATA_VDC: R56.2 TP1.1 ; port MDATA_VDC
U_BOT: C75.1 R12.2 TP19.1 U24.11(GWN) ; port U_BOT
U_PHASE: J4.1 R120.2 ; port U_PHASE
U_PHASE_REF: R120.1 TP32.1 U24.21(W) U24.22(W) U24.23(W) ; port U_PHASE_REF
U_TOP: C74.1 R112.2 TP17.1 U24.9(GWP) ; port U_TOP
V_BOT: C76.1 R38.2 TP21.1 U24.7(GVN) ; port V_BOT
V_TOP: C73.1 R32.2 TP14.1 U24.5(GVP) ; port V_TOP
W_BOT: C77.1 R26.2 TP23.1 U24.3(GUN) ; port W_BOT
W_PHASE: J4.3 R118.2 ; port W_PHASE
W_PHASE_REF: R118.1 TP28.1 TP29.1 U24.27(U) U24.28(U) U24.29(U) ; port W_PHASE_REF
W_TOP: C72.1 R20.2 TP12.1 U24.1(GUP) ; port W_TOP
NetC81_1: C81.1 R83.2 U12.2(AINP)
NetC81_2: C81.2 R82.2 U12.3(AINN)
NetC92_1: C92.1 R93.2 U15.2(AINP)
NetC92_2: C92.2 R92.2 U15.3(AINN)
NetC94_2: C94.2 R81.2 R82.1 R107.2
NetC96_1: C96.1 C97.1 R110.2 U23.2(IN)
NetD9_2: D9.2(A) J3.1 Q1.2(C)
NetD10_2: D10.2(A) D11.1(K)
NetD11_2: D11.2(A) R108.1 R122.2
NetJ4_2: J4.2 TP31.1 U24.24(V) U24.25(V) U24.26(V)
NetR40_1: R40.1 R106.2 U9.3(IN+) U24.19(TH1)
NetR40_2: R40.2 R93.1 TP37.1 U9.1(OUT) U9.4(IN-)
NetR45_2: R45.2 R48.1
NetR48_2: R48.2 R49.1
NetR49_2: R49.2 R50.1
NetR50_2: R50.2 R57.2
NetR51_2: R51.2 R54.1
NetR54_2: R54.2 R57.1
NetR55_1: R55.1 U12.7(CLKIN)
NetR56_1: R56.1 U12.6(DOUT)
NetR58_1: R58.1 U15.7(CLKIN)
NetR59_1: R59.1 U15.6(DOUT)
NetR83_1: R83.1 R109.2 R129.1
NetR90_1: R90.1 R91.2 R92.1
NetR98_1: R98.1 R108.2
NetR122_1: R122.1 R125.2
NetR125_1: R125.1 R127.2
NetR127_1: R127.1 R128.2
NetR128_1: R128.1 R129.2

Not connected (* = marked no-connect by the designer): U23 4(NC)* 5(NC)*

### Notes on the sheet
- Bleeder resistor network
- Three Phase Inverter
- Fuse holder
- Braking Chopper
- Text
- Module Temperature Sensing
- DC link voltage sensing
- Secondary Side 3.3V Supply

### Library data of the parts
C58 C61 C64 C67 C95 C96 = C2012X7R1V475K125AC: CAP, CERM, 4.7 µF, 35 V, +/- 10%, X7R, 0805; Manufacturer: TDK; Polarized: N; CompType: Capacitor; Value: 4.7uF; U/M: EA; Cap_F: 0.0000047; Tolerance_%: 10; ESR_ohm: 0.002346; Value1: 0.002346 ohm; VDC_V: 35; Value2: 35V; IRMS_A: 4.26021; TaMin_C: -55; TaMax_C: 125; Cap_Case: 0805; AEC Category: Q200; SizeArea_mm2: 2.5; SizeAreaWB_mm2: 6.75; SizeX_mm: 2; SizeY_mm: 1.25; SizeZ_mm: 1.45
C63 C70 C79 C82 C91 C94 C97 = C1608X7R1H104K: as C6 on sheet TIDA-00914-E1_Gate drivers
C72-C78 = CGA3E2C0G1H103J080AA: CAP, CERM, 0.01 µF, 50 V, +/- 5%, C0G/NP0, AEC-Q200 Grade 1, 0603; Manufacturer: TDK; Polarized: N; CompType: Capacitor; Value: 0.01uF; U/M: EA; Cap_F: 0.00000001; Tolerance_%: 5; Value1: Unknown; VDC_V: 50; Value2: 50V; TaMin_C: -55; TaMax_C: 125; SizeArea_mm2: 1.28; SizeAreaWB_mm2: 4.68; SizeX_mm: 1.6; SizeY_mm: 0.8; SizeZ_mm: 1; AEC Category: Q200; AEC Qualified: Y
C81 C92 = GRM1885C1H470JA01D: CAP, CERM, 47 pF, 50 V, +/- 5%, C0G/NP0, 0603; Manufacturer: MuRata; Polarized: N; CompType: Capacitor; Value: 47pF; U/M: EA; Cap_F: 0.000000000047; Tolerance_%: 5; Value1: Unknown; VDC_V: 50; Value2: 50V; TaMin_C: -55; TaMax_C: 125; AEC Category: Q200; SizeArea_mm2: 1.28; SizeAreaWB_mm2: 4.68; SizeX_mm: 1.6; SizeY_mm: 0.8; SizeZ_mm: 1
C111 C112 = B32774D1305K000: CAP, Film, 3 µF, 1300 V, +/- 10%, 0.016 ohm, TH; Manufacturer: TDK; Polarized: N; CompType: Capacitor; Value: 3uF; U/M: EA; Cap_F: 0.000003; Tolerance_%: 10; VDC_V: 1300; Value2: 1300V; ESR_ohm: 0.016; IRMS_A: 7; TaMin_C: -40; TaMax_C: 105; Cap_Case: 31.5x18x27.5mm; AEC Category: Q200
D9 = FFH60UP40S: Diode, Ultrafast, 1200 V, 30 A, TH; Manufacturer: Fairchild Semiconductor; U/M: EA; Vf_V: 1.3; Value2: 1.3V; Io_A: 60; Vr_V: 400; TJmax_C: 150; RJC_CperW: 0.2; SizeAreaWB_mm2: 125.125; SizeArea_mm2: 79.375; SizeX_mm: 15.875; SizeY_mm: 5; SizeZ_mm: 25.96; AEC Category: Q101; AEC Qualified: N
D10 D11 = 1SMB5956BT3G: Diode, Zener, 200 V, 550 mW, SMB; Manufacturer: ON Semiconductor; SymbolCreator: a0412235; U/M: EA; Power_W: 0.55; Vz_V: 200; Value1: 0.55W; RJA_CperW: 226; AEC Category: Q101
J3 = 1902547: Terminal Block, 9.52mm, 2x1, R/A, TH; Manufacturer: Phoenix Contact; SymbolCreator: a0412235; Pitch_mm: 9.52; Gender: Female; Row_Count: 1; Current_A: 32; Voltage_V: 1000; Cert_UL: Y
J4 = 1904150: Terminal Block, 9.52mm, 3x1, R/A, TH; Manufacturer: Phoenix Contact; SymbolCreator: a0412235; Pitch_mm: 9.52; Gender: Female; Row_Count: 1; Cert_UL: Y
J8 = 1902547: Terminal Block, 9.52mm, 2x1, R/A, TH; Manufacturer: Phoenix Contact; SymbolCreator: a0412235; Pitch_mm: 9.52; Gender: Female; Row_Count: 1; Cert_UL: Y
Q1 = IGW03N120H2, Infineon Technologies: Transistor, IGBT, 1200 V, 9.9 A, TO-247; SymbolCreator: Altium; PNP: 0; Vceo_V: 1200; Vcesat1_V: 2.8; IcRated_A: 9.6; TaMin_C: -40; TaMax_C: 150; CompType: BJT; U/M: EA; AEC Category: Q101
R12 R20 R26 R32 R38 R96 R112 = CRCW060310K0JNEA: RES, 10 k, 5%, 0.1 W, 0603; Manufacturer: Vishay-Dale; CompType: Resistor; Value: 10k; Res_ohm: 10000; Value_Code: 10k0; Tolerance_%: 5; Power_W: 0.1; Value2: 0.1W; VDC_V: 75; TempCo: 200 ppm/C; EIA_Code: E24; U/M: EA; AEC Category: Q200
R40 R82 R83 R91-R93 = CRCW06030000Z0EA: as R2 on sheet TIDA-00914-E1_Gate drivers
R45 R48-R51 R54 R57 = ERJ-8ENF3573V: RES, 100 k, 5%, 0.75 W, 1206; Manufacturer: Vishay; CompType: Resistor; Value: 100k; Res_ohm: 100000; Tolerance_%: 5; Power_W: 0.75; Value2: 0.75W; VDC_V: 200; TempCo: 200 ppm/C; SizeArea_mm2: 5.12; SizeX_mm: 3.2; SizeY_mm: 1.6; SizeZ_mm: 1.35; EIA_Code: E96; U/M: EA; AEC Category: Q200
R55 R56 R58 R59 = CRCW060322R0JNEA: RES, 22, 5%, 0.1 W, 0603; Manufacturer: Vishay-Dale; CompType: Resistor; Value: 22; Value_Code: 22R0; Tolerance_%: 5; Power_W: 0.1; Value2: 0.1W; VDC_V: 75; TempCo: 200 ppm/C; SizeArea_mm2: 1.28; SizeX_mm: 1.6; SizeY_mm: 0.8; SizeZ_mm: 1; EIA_Code: E24; U/M: EA; AEC Category: Q200
R81 = CRCW060312K1FKEA: RES, 12.1 k, 1%, 0.1 W, 0603; Manufacturer: Vishay-Dale; CompType: Resistor; Value: 12.1k; Res_ohm: 12100; Value_Code: 12k1; Tolerance_%: 1; Power_W: 0.1; Value2: 0.1W; VDC_V: 75; TempCo: 100 ppm/C; EIA_Code: E96; U/M: EA; AEC Category: Q200; SizeArea_mm2: 1.28; SizeX_mm: 1.6; SizeY_mm: 0.8
R90 R107 R109 = CRCW06031K00FKEA: as R8 on sheet TIDA-00914-E1_Gate drivers
R98 R108 R122 R125 R127-R129 = RC1206FR-07820KL: RES, 820 k, 1%, 0.25 W, 1206; Manufacturer: Yageo America; CompType: Resistor; Value: 820k; Res_ohm: 820000; Tolerance_%: 1; Power_W: 0.25; Value2: 0.25W; VDC_V: 200; TempCo: 100 ppm/C; SizeArea_mm2: 5.12; SizeX_mm: 3.2; SizeY_mm: 1.6; SizeZ_mm: 1.35; U/M: EA; AEC Category: Q200
R106 = CRCW0603160KFKEA: RES, 160 k, 1%, 0.1 W, 0603; Manufacturer: Vishay-Dale; CompType: Resistor; Value: 160k; Res_ohm: 160000; Tolerance_%: 1; Power_W: 0.1; Value2: 0.1W; VDC_V: 75; TempCo: 100 ppm/C; SizeArea_mm2: 1.28; SizeX_mm: 1.6; SizeY_mm: 0.8; U/M: EA; AEC Category: Q200
R110 = CRCW06030000Z0EA: RES, 0, 5%, 0.1 W, 0603; Manufacturer: Vishay-Dale; CompType: Resistor; Value: 0; Value_Code: 0000; Tolerance_%: 5; Power_W: 0.1; Value2: 0.1W; VDC_V: 75; TempCo: 200 ppm/C; EIA_Code: E24; U/M: EA; AEC Category: Q200
R118 R120 = PU5931FKHPA0U2L: RES, 0.004, 1%, 7 W, AEC-Q200 Grade 0, 15x7.75mm; Manufacturer: Yageo America; CompType: Resistor; Value: 0.004; Value_Code: L2000; Tolerance_%: 1; Power_W: 7; Value2: 7W; TempCo: 225 ppm/C; SizeArea_mm2: 116.25; SizeAreaWB_mm2: 165.75; SizeX_mm: 15; SizeY_mm: 7.75; SizeZ_mm: 1.46; EIA_Code: E96; U/M: EA; AEC Category: Q200; AEC Qualified: Y; AEC Grade: 0
TP1-TP3 TP7 TP15 TP29 TP31 TP32 TP36 TP37 = 5000: Test Point, Miniature, Red, TH; Manufacturer: Keystone; CompType: Test Point Loop; ContactFinish: Silver
TP12-TP14 TP16-TP28 TP30 TP33-TP35 = TESTPOINT: TEST POINT.  No entry in BOM.
U9 = LPV521MG: Nanopower 400nA, 1.8V, R-R I/O CMOS Op Amp, DCK0005A; Manufacturer: Texas Instruments; CompType: OpAmp IC
U12 U15 = AMC1306M05DWVR: Small, High-Precision, Reinforced Isolated Delta-Sigma Modulator with Manchester Coded Output, DWV0008A; Manufacturer: Texas Instruments; SymbolCreator: Altium; SizeArea_mm2: 67.275; SizeAreaWB_mm2: 105.975; SizeX_mm: 11.5; SizeY_mm: 5.85; SizeZ_mm: 2.8; CompType: IC; U/M: EA
U23 = TLV70433DBVR: Single Output LDO, 150 mA, Fixed 3.3 V Output, 2.5 to 24 V Input, with Ultra-Low IQ, 5-pin SOT-23 (DBV), -40 to 125 degC, Green (RoHS & no Sb/Br); Manufacturer: Texas Instruments; Alternate PartNumber: Equivalent; Accuracy(%): 2; Fixed Output Options(V): 3.3; Iout(Max)(A): 0.15; Iq(Typ)(mA): 0.003; SubFamily: Single Channel LDO; Vdo(Typ)(mV): 400; Vin(Max)(V): 24; Vin(Min)(V): 2.5
U24 = CM100TX-24S1: IGBT Module,High Power Switching Use Insulated Type, TH; Manufacturer: Mitsubishi; SymbolCreator: a0411947; SizeAreaWB_mm2: 7916.8; SizeArea_mm2: 7545.4; SizeX_mm: 121.7; SizeY_mm: 62; SizeZ_mm: 17.5
XF1 XF2 = 3566: Fuse Holder, 5AG, TH; Manufacturer: Keystone; SymbolCreator: a0411947

## Sheet TIDA-00914-E1_Current sense, MCU Interface.SchDoc: Current sense , MCU interface
size 431 x 279 mm; Date: Not shown in title block; ApprovedBy: Not shown in title block; CheckedBy: Not shown in title block; Author: Not shown in title block; CompanyName: Not shown in title block; DrawnBy: PN; Engineer: PN; Organization: Not shown in title block; Address1: Not shown in title block; Address2: Not shown in title block; Address3: Not shown in title block; Address4: Not shown in title block; DocumentNumber: 1; Revision: Use project parameter SCH_Rev; SheetNumber: 4; SheetTotal: 5; PageSetup: Record=PageOptions¦CenterHorizontal=True¦CenterVertical=True¦PrintScale=1.00¦XCorrection=1.00¦YCorrection=1.00¦PrintKind=0¦BorderSize=5000000¦LeftOffset=0¦BottomOffset=0¦Orientation=2¦PaperLength=1000¦PaperWidth=1000¦Scale=100¦PaperSource=15¦PrintQuality=600¦MediaType=1¦DitherType=10¦PaperKind=Letter¦PrintScaleMode=1
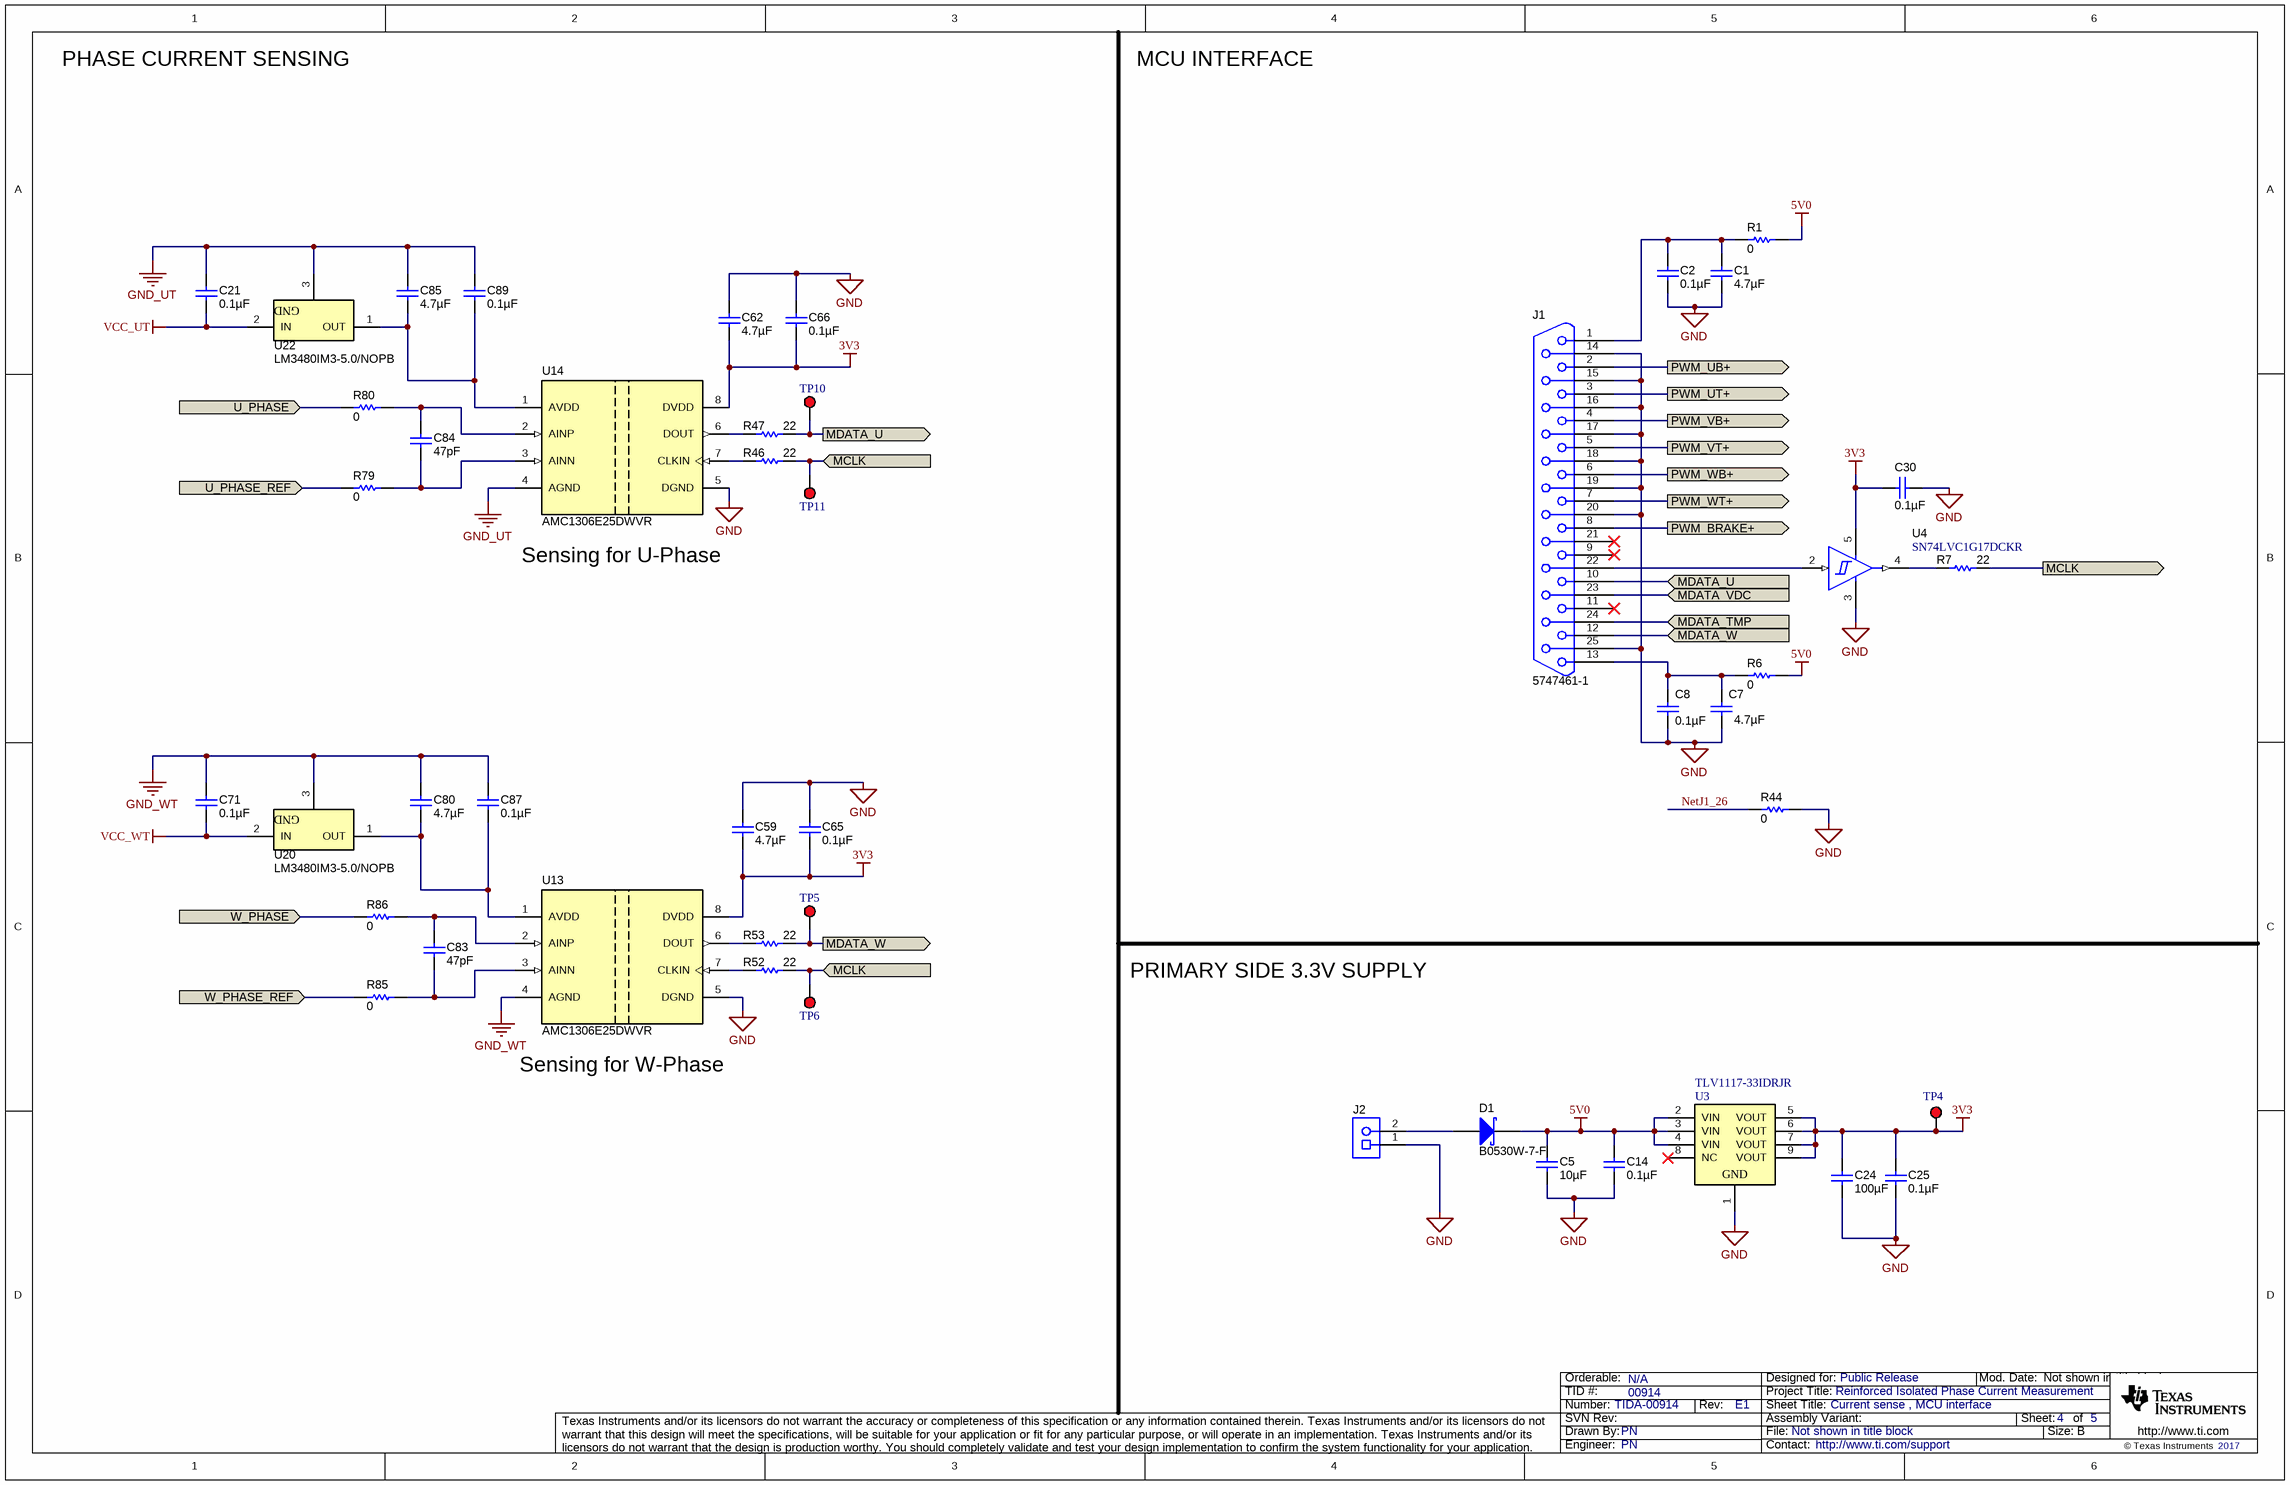
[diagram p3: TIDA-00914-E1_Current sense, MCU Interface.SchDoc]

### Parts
C1  ValueDisplayed: 4.7µF  [0805_HV]  (hidden comment: C2012X7R1V475K125AC)
C2  ValueDisplayed: 0.1µF  [0603]  (hidden comment: C1608X7R1H104K)
C5  ValueDisplayed: 10µF  [1210_280]  (hidden comment: UMK325AB7106KM-T)
C7  ValueDisplayed: 4.7µF  [0805_HV]  (hidden comment: C2012X7R1V475K125AC)
C8  ValueDisplayed: 0.1µF  [0603]  (hidden comment: C1608X7R1H104K)
C14  ValueDisplayed: 0.1µF  [0603]  (hidden comment: C1608X7R1H104K)
C21  ValueDisplayed: 0.1µF  [0603]  (hidden comment: C1608X7R1H104K)
C24  ValueDisplayed: 100µF  [1210_270]  (hidden comment: C1210C107M4PAC7800)
C25  ValueDisplayed: 0.1µF  [0603]  (hidden comment: C1608X7R1H104K)
C30  ValueDisplayed: 0.1µF  [0603]  (hidden comment: C1608X7R1H104K)
C59  ValueDisplayed: 4.7µF  [0805_HV]  (hidden comment: C2012X7R1V475K125AC)
C62  ValueDisplayed: 4.7µF  [0805_HV]  (hidden comment: C2012X7R1V475K125AC)
C65  ValueDisplayed: 0.1µF  [0603]  (hidden comment: C1608X7R1H104K)
C66  ValueDisplayed: 0.1µF  [0603]  (hidden comment: C1608X7R1H104K)
C71  ValueDisplayed: 0.1µF  [0603]  (hidden comment: C1608X7R1H104K)
C80  ValueDisplayed: 4.7µF  [0805_HV]  (hidden comment: C2012X7R1V475K125AC)
C83  ValueDisplayed: 47pF  [0603]  (hidden comment: GRM1885C1H470JA01D)
C84  ValueDisplayed: 47pF  [0603]  (hidden comment: GRM1885C1H470JA01D)
C85  ValueDisplayed: 4.7µF  [0805_HV]  (hidden comment: C2012X7R1V475K125AC)
C87  ValueDisplayed: 0.1µF  [0603]  (hidden comment: C1608X7R1H104K)
C89  ValueDisplayed: 0.1µF  [0603]  (hidden comment: C1608X7R1H104K)
D1  B0530W-7-F  [SOD-123]
J1  5747461-1  [Amp_DB25]
J2  282834-2  [TEC_282834-2]  (value not drawn)
R1  ValueDisplayed: 0  [1206]  (hidden comment: CRCW12060000Z0EA)
R6  ValueDisplayed: 0  [1206]  (hidden comment: CRCW12060000Z0EA)
R7  ValueDisplayed: 22  [0603]  (hidden comment: CRCW060322R0JNEA)
R44  ValueDisplayed: 0  [1206]  (hidden comment: CRCW12060000Z0EA)
R46  ValueDisplayed: 22  [0603]  (hidden comment: CRCW060322R0JNEA)
R47  ValueDisplayed: 22  [0603]  (hidden comment: CRCW060322R0JNEA)
R52  ValueDisplayed: 22  [0603]  (hidden comment: CRCW060322R0JNEA)
R53  ValueDisplayed: 22  [0603]  (hidden comment: CRCW060322R0JNEA)
R79  ValueDisplayed: 0  [0603]  (hidden comment: CRCW06030000Z0EA)
R80  ValueDisplayed: 0  [0603]  (hidden comment: CRCW06030000Z0EA)
R85  ValueDisplayed: 0  [0603]  (hidden comment: CRCW06030000Z0EA)
R86  ValueDisplayed: 0  [0603]  (hidden comment: CRCW06030000Z0EA)
TP4  5000  [Keystone5000]  (value not drawn)
TP5  5000  [Keystone5000]  (value not drawn)
TP6  5000  [Keystone5000]  (value not drawn)
TP10  5000  [Keystone5000]  (value not drawn)
TP11  5000  [Keystone5000]  (value not drawn)
U3  TLV1117-33IDRJR  [DRJ0008A]
U4  SN74LVC1G17DCKR  [DCK0005A_N]
U13  AMC1306E25DWVR  [DWV0008A]
U14  AMC1306E25DWVR  [DWV0008A]
U20  LM3480IM3-5.0/NOPB  [MF03A_N]
U22  LM3480IM3-5.0/NOPB  [MF03A_N]

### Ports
MCLK (in), MCLK (out), MDATA_TMP (in), MDATA_U (in), MDATA_U (out), MDATA_VDC (in), MDATA_W (in), MDATA_W (out), PWM_BRAKE+ (out), PWM_UB+ (out), PWM_UT+ (out), PWM_VB+ (out), PWM_VT+ (out), PWM_WB+ (out), PWM_WT+ (out), U_PHASE (in), U_PHASE_REF (in), W_PHASE (in), W_PHASE_REF (in)

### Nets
3V3: C24.1 C25.1 C30.1 C59.2 C62.2 C65.2 C66.2 TP4.1 U3.5(VOUT) U3.6(VOUT) U3.7(VOUT) U3.9(VOUT) U4.5(VCC) U13.8(DVDD) U14.8(DVDD)
5V0: C5.1 C14.1 D1.1(K) R1.1 R6.1 U3.2(VIN) U3.3(VIN) U3.4(VIN)
GND: C1.1 C2.1 C5.2 C7.2 C8.2 C14.2 C24.2 C25.2 C30.2 C59.1 C62.1 C65.1 C66.1 J1.14 J1.15 J1.16 J1.17 J1.18 J1.19 J1.20 J1.25 J2.1 R44.1 U3.1(GND) U4.3(GND) U13.5(DGND) U14.5(DGND)
GND_UT: C21.1 C85.1 C89.1 U14.4(AGND) U22.3(GND)
GND_WT: C71.1 C80.1 C87.1 U13.4(AGND) U20.3(GND)
VCC_UT: C21.2 U22.2(IN)
VCC_WT: C71.2 U20.2(IN)
MCLK: R7.2 R46.2 R52.2 TP6.1 TP11.1 ; port MCLK
MDATA_TMP: J1.24 ; port MDATA_TMP
MDATA_U: J1.10 R47.2 TP10.1 ; port MDATA_U
MDATA_VDC: J1.23 ; port MDATA_VDC
MDATA_W: J1.12 R53.2 TP5.1 ; port MDATA_W
NetJ1_26: R44.2
PWM_BRAKE+: J1.8 ; port PWM_BRAKE+
PWM_UB+: J1.2 ; port PWM_UB+
PWM_UT+: J1.3 ; port PWM_UT+
PWM_VB+: J1.4 ; port PWM_VB+
PWM_VT+: J1.5 ; port PWM_VT+
PWM_WB+: J1.6 ; port PWM_WB+
PWM_WT+: J1.7 ; port PWM_WT+
U_PHASE: R80.1 ; port U_PHASE
U_PHASE_REF: R79.1 ; port U_PHASE_REF
W_PHASE: R86.1 ; port W_PHASE
W_PHASE_REF: R85.1 ; port W_PHASE_REF
NetC1_2: C1.2 C2.2 J1.1 R1.2
NetC7_1: C7.1 C8.1 J1.13 R6.2
NetC80_2: C80.2 C87.2 U13.1(AVDD) U20.1(OUT)
NetC83_1: C83.1 R86.2 U13.2(AINP)
NetC83_2: C83.2 R85.2 U13.3(AINN)
NetC84_1: C84.1 R80.2 U14.2(AINP)
NetC84_2: C84.2 R79.2 U14.3(AINN)
NetC85_2: C85.2 C89.2 U14.1(AVDD) U22.1(OUT)
NetD1_2: D1.2(A) J2.2
NetJ1_22: J1.22 U4.2(A)
NetR7_1: R7.1 U4.4(Y)
NetR46_1: R46.1 U14.7(CLKIN)
NetR47_1: R47.1 U14.6(DOUT)
NetR52_1: R52.1 U13.7(CLKIN)
NetR53_1: R53.1 U13.6(DOUT)

Not connected (* = marked no-connect by the designer): J1 9* 11* 21*; U3 8(NC)*

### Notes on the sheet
- PHASE CURRENT SENSING
- MCU INTERFACE
- Sensing for U-Phase
- PRIMARY SIDE 3.3V SUPPLY
- Sensing for W-Phase

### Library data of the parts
C1 C7 C59 C62 C80 C85 = C2012X7R1V475K125AC: as C58 on sheet TIDA-00914-E1_IGBT Module, Temp and DC link sense
C2 C8 C14 C21 C25 C30 C65 C66 C71 C87 C89 = C1608X7R1H104K: as C6 on sheet TIDA-00914-E1_Gate drivers
C5 = UMK325AB7106KM-T: CAP, CERM, 10 µF, 50 V, +/- 10%, X7R, 1210; Manufacturer: Taiyo Yuden; Polarized: N; CompType: Capacitor; Value: 10uF; U/M: EA; Cap_F: 0.00001; Tolerance_%: 10; Value1: Unknown; VDC_V: 50; Value2: 50V; TaMin_C: -55; TaMax_C: 125; Cap_Case: 1210; SizeArea_mm2: 8; SizeAreaWB_mm2: 14.7; SizeX_mm: 3.2; SizeY_mm: 2.5; SizeZ_mm: 2.8; AEC Category: Q200
C24 = C1210C107M4PAC7800: CAP, CERM, 100 µF, 16 V, +/- 20%, X5R, 1210; Manufacturer: Kemet; Polarized: N; CompType: Capacitor; Value: 100uF; U/M: EA; Cap_F: 0.0001; Tolerance_%: 20; Value1: Unknown; VDC_V: 16; Value2: 16V; TaMin_C: -55; TaMax_C: 85; Cap_Case: 1210; SizeArea_mm2: 8; SizeAreaWB_mm2: 14.7; SizeX_mm: 3.2; SizeY_mm: 2.5; SizeZ_mm: 2.7; AEC Category: Q200
C83 C84 = GRM1885C1H470JA01D: as C81 on sheet TIDA-00914-E1_IGBT Module, Temp and DC link sense
D1 = B0530W-7-F: Diode, Schottky, 30 V, 0.5 A, SOD-123; Manufacturer: Diodes Inc.; U/M: EA; Vf_V: 0.43; Value: 30V; Value1: 0.5A; Value2: 0.43V; Io_A: 0.5; Vr_V: 30; TJmax_C: 125; SizeAreaWB_mm2: 13.095; SizeArea_mm2: 6.545; SizeX_mm: 3.85; SizeY_mm: 1.7; SizeZ_mm: 1.35; AEC Category: Q101
J1 = 5747461-1: Connector, TH, DB25 parallel port, plastic, right angle; Manufacturer: AMP
J2 = 282834-2: Terminal Block, 2x1, 2.54mm, TH; Manufacturer: TE Connectivity; SymbolCreator: a0412235
R1 R6 R44 = CRCW12060000Z0EA: as R3 on sheet TIDA-00914-E1_Gate drivers
R7 R46 R47 R52 R53 = CRCW060322R0JNEA: as R55 on sheet TIDA-00914-E1_IGBT Module, Temp and DC link sense
R79 R80 R85 R86 = CRCW06030000Z0EA: as R110 on sheet TIDA-00914-E1_IGBT Module, Temp and DC link sense
TP4-TP6 TP10 TP11 = 5000: as TP1 on sheet TIDA-00914-E1_IGBT Module, Temp and DC link sense
U3 = TLV1117-33CDRJR: LDO with 4.7 to 15 V Input and 3.3 V Output, -40 to 125 degC, 8-Pin SON (DRJ), Green (RoHS & no Sb/Br); Manufacturer: Texas Instruments; Alternate PartNumber: Equivalent; Iout(Max)(A): 0.8; Iq(Typ)(mA): 5; SubFamily: Single Channel LDO; Vin(Max)(V): 15; Vin(Min)(V): 4.7; Vout(Max)(V): 3.3
U4 = SN74LVC1G17DCKR: SINGLE SCHMITT-TRIGGER BUFFER, DCK0005A (SOT-5); Alternate PartNumber: SN74LVC1G17DCKT; Manufacturer: Texas Instruments; SymbolCreator: a0799628; SizeArea_mm2: 4.2; SizeAreaWB_mm2: 9.3; SizeX_mm: 2.1; SizeY_mm: 2; SizeZ_mm: 1.1; CompType: IC; U/M: EA
U13 U14 = AMC1306M05DWVR: as U12 on sheet TIDA-00914-E1_IGBT Module, Temp and DC link sense
U20 U22 = LM3480IM3-5.0/NOPB: 100 mA, Quasi Low-Dropout Linear Voltage Regulator, 3-pin SOT-23, Pb-Free; Manufacturer: Texas Instruments; PackageTopMarking: L0B*XTT; PowerWise: N; CompType: LDO IC

## Sheet TIDA-00914-E1_EVM_Hardware.SchDoc: Hardware
size 431 x 279 mm; Date: Not shown in title block; ApprovedBy: Not shown in title block; CheckedBy: Not shown in title block; Author: Not shown in title block; CompanyName: Not shown in title block; DrawnBy: PN; Engineer: PN; Organization: Not shown in title block; Address1: Not shown in title block; Address2: Not shown in title block; Address3: Not shown in title block; Address4: Not shown in title block; DocumentNumber: 1; Revision: Use project parameter SCH_Rev; SheetNumber: 5; SheetTotal: 5; PageSetup: Record=PageOptions¦CenterHorizontal=True¦CenterVertical=True¦PrintScale=1.00¦XCorrection=1.00¦YCorrection=1.00¦PrintKind=0¦BorderSize=5000000¦LeftOffset=0¦BottomOffset=0¦Orientation=2¦PaperLength=1000¦PaperWidth=1000¦Scale=100¦PaperSource=15¦PrintQuality=600¦MediaType=1¦DitherType=10¦PaperKind=Letter¦PrintScaleMode=1
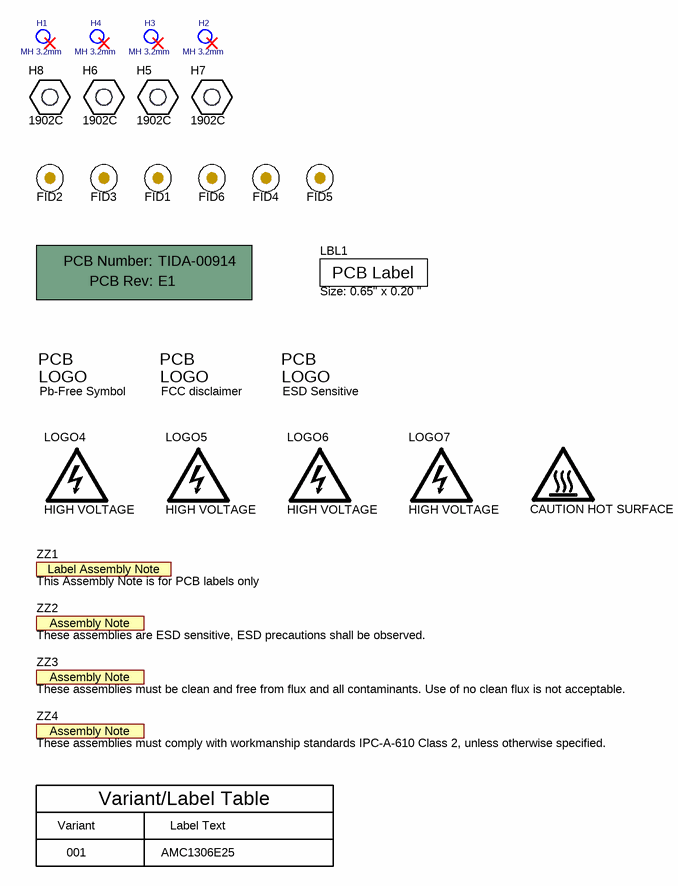
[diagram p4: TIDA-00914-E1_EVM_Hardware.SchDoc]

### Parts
!PCB1  Printed Circuit Board  (value not drawn)  (mechanical)
CAUTION_HOT_SURFACE  CAUTION HOT SURFACE  [IEC_HotSurface_Medium]  (value not drawn)  (no BOM)
ESD_Sensitive  ESD Susceptible  [ESD_Overlay_Medium]  (value not drawn)  (no BOM)
FID1  Fiducial  [Fiducial10-20]  (value not drawn)
FID2  Fiducial  [Fiducial10-20]  (value not drawn)
FID3  Fiducial  [Fiducial10-20]  (value not drawn)
FID4  Fiducial  [Fiducial10-20]  (value not drawn)
FID5  Fiducial  [Fiducial10-20]  (value not drawn)
FID6  Fiducial  [Fiducial10-20]  (value not drawn)
H1  MH 3.2mm  [MH3.2_H5_W6_KO8_STARHEAD]
H2  MH 3.2mm  [MH3.2_H5_W6_KO8_STARHEAD]
H3  MH 3.2mm  [MH3.2_H5_W6_KO8_STARHEAD]
H4  MH 3.2mm  [MH3.2_H5_W6_KO8_STARHEAD]
H5  1902C  [Keystone_1902C]
H6  1902C  [Keystone_1902C]
H7  1902C  [Keystone_1902C]
H8  1902C  [Keystone_1902C]
LBL1  Size: 0.65" x 0.20 "  [Label_650x200]
Logo2  Pb-Free Symbol  [Pb-Free_Overlay_Small]  (no BOM)
Logo3  FCC disclaimer  [FCC_disclaimer]  (no BOM)
LOGO4  HIGH VOLTAGE  [IEC_HighVoltage_medium]  (no BOM)
LOGO5  HIGH VOLTAGE  [IEC_HighVoltage_medium]  (no BOM)
LOGO6  HIGH VOLTAGE  [IEC_HighVoltage_medium]  (no BOM)
LOGO7  HIGH VOLTAGE  [IEC_HighVoltage_medium]  (no BOM)
ZZ1  This Assembly Note is for PCB labels only  [AssemblyNoteLabel]  (no BOM)
ZZ2  These assemblies are ESD sensitive, ESD precautions shall be observed.  [AssemblyNote]  (no BOM)
ZZ3  These assemblies must be clean and free from flux and all contaminants. Use of no clean flux is not acceptable.  [AssemblyNote]  (no BOM)
ZZ4  These assemblies must comply with workmanship standards IPC-A-610 Class 2, unless otherwise specified.  [AssemblyNote]  (no BOM)

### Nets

Not connected (* = marked no-connect by the designer): H1 1*; H2 1*; H3 1*; H4 1*

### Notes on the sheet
- Variant/Label Table
- Variant
- 001
- Label Text
- AMC1306E25

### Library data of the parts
!PCB1 = PCB: Manufacturer: Any; PartNumber: TIDA-00914; SymbolCreator: a0412235
CAUTION_HOT_SURFACE = IEC_HotSurface: IEC 61010-1 Hot Surface Warning; SymbolCreator: a0412235
ESD_Sensitive = ESD_Susceptible: ESD Susceptible Symbol; SymbolCreator: a0412235
FID1-FID6 = Fiducial: Fiducial mark.  There is nothing to buy or mount.; SymbolCreator: codlsc
H1-H4 = MH 3_0.5MM: Mountin hole, NPTH Drill 3.2mm
H5-H8 = 1902C: Standoff, Hex, 0.5"L #4-40 Nylon; Manufacturer: Keystone; CompType: Hardware
LBL1 = THT-14-423-10: Thermal Transfer Printable Labels, 0.650" W x 0.200" H - 10,000 per roll; Manufacturer: Brady; SymbolCreator: a0412235; CompType: Label
Logo2 = Pb-Free: SymbolCreator: a0412235
Logo3 = FCC_disclaimer: SymbolCreator: codlsc
LOGO4-LOGO7 = IEC_HighVoltage: IEC 61010-1 High Voltage Warning; SymbolCreator: a0412235
ZZ1 = AssemblyNoteLabel: SymbolCreator: a0412235
ZZ2-ZZ4 = AssemblyNote: SymbolCreator: codlsc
